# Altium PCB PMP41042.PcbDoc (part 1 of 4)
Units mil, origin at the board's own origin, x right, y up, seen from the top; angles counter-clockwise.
Board outline 9847.6 x 4445 mil, 6 copper layers (Top Layer, Layer 1, Layer 2, Layer 3, Layer 4, Bottom Layer), stack 32.112 mil thick; 329 components, 129 nets, 1246 pads, 863 vias.
Unrouted connection lines stored in the file: 6.
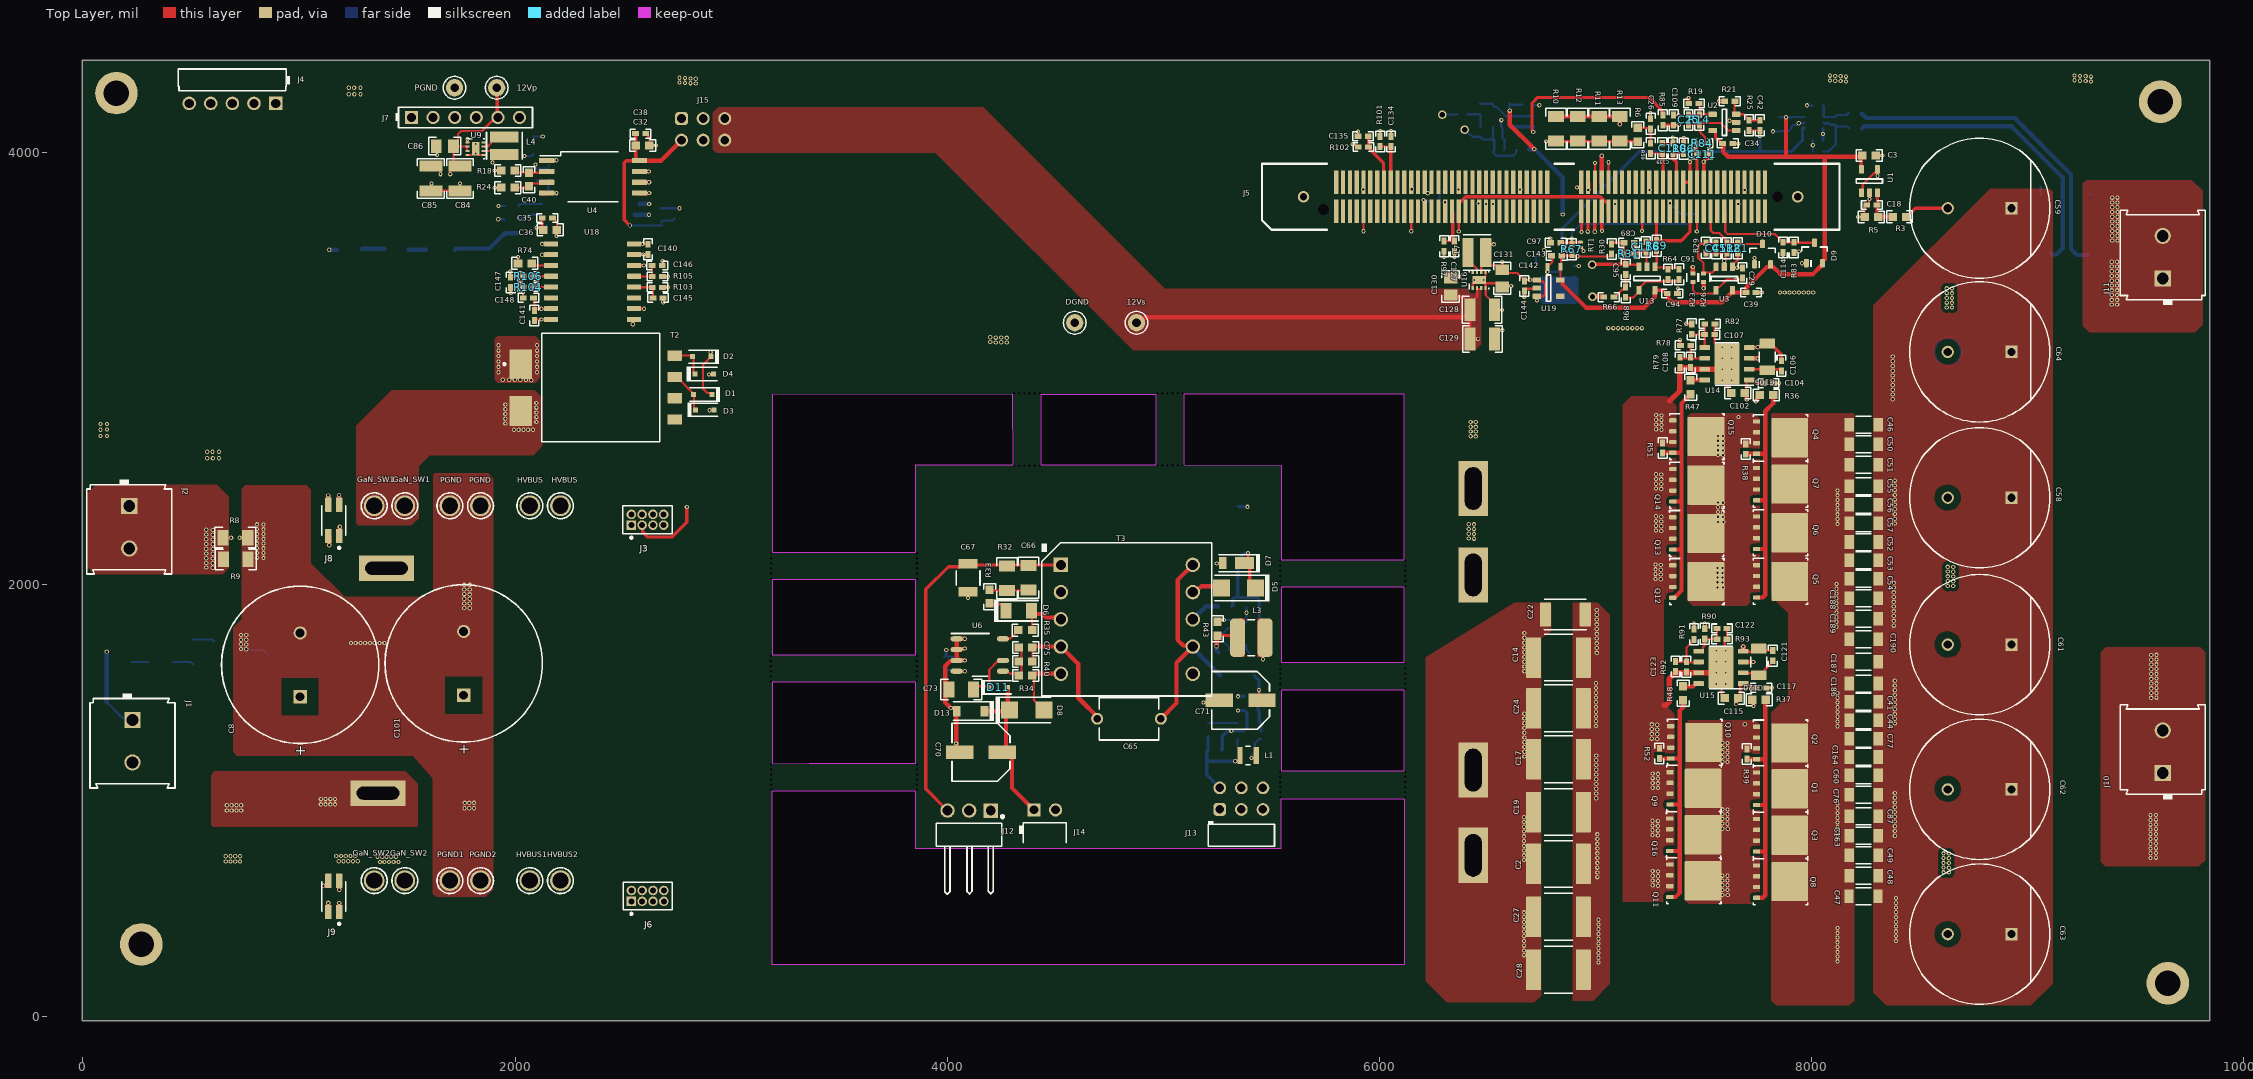
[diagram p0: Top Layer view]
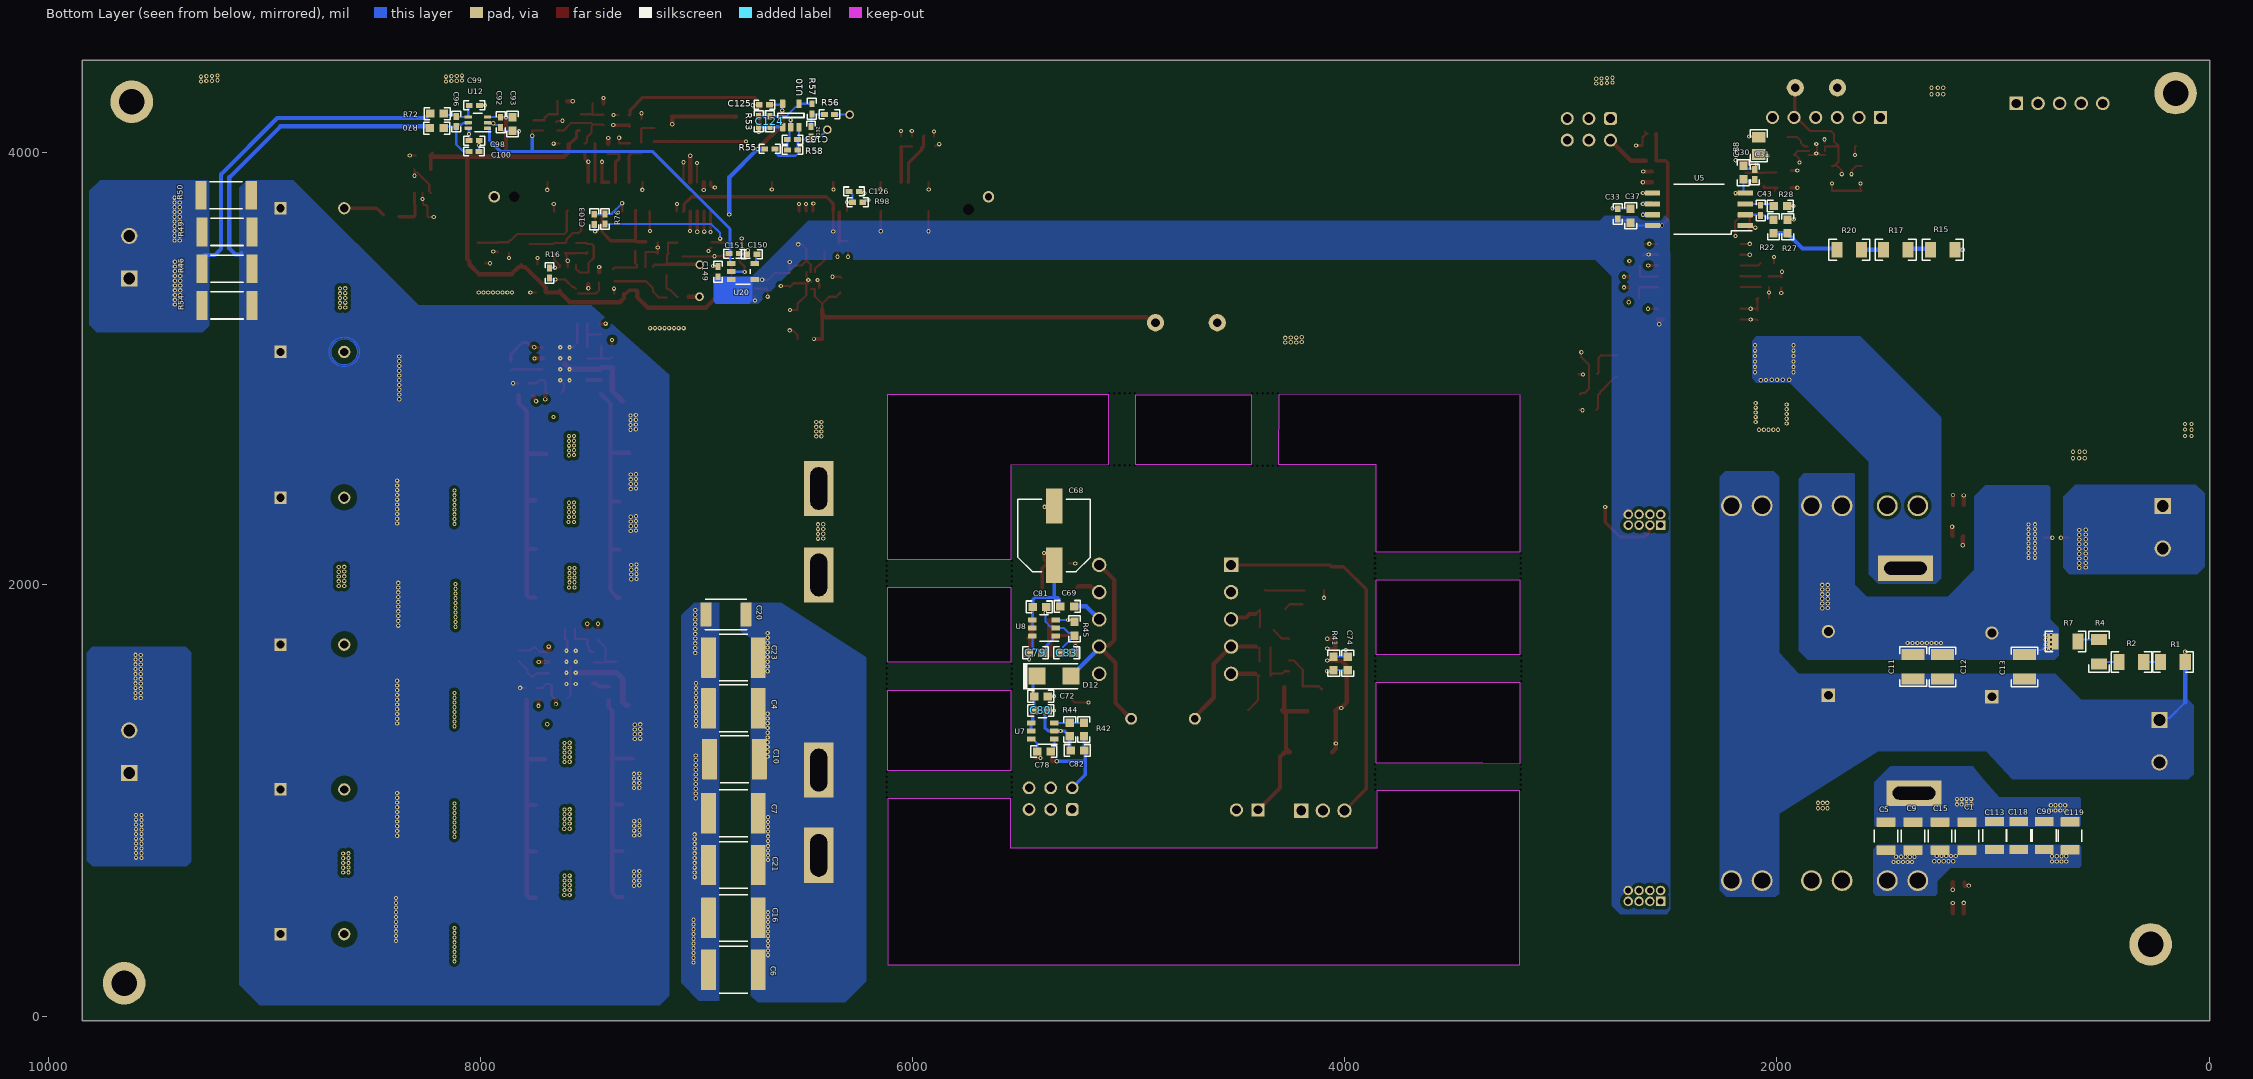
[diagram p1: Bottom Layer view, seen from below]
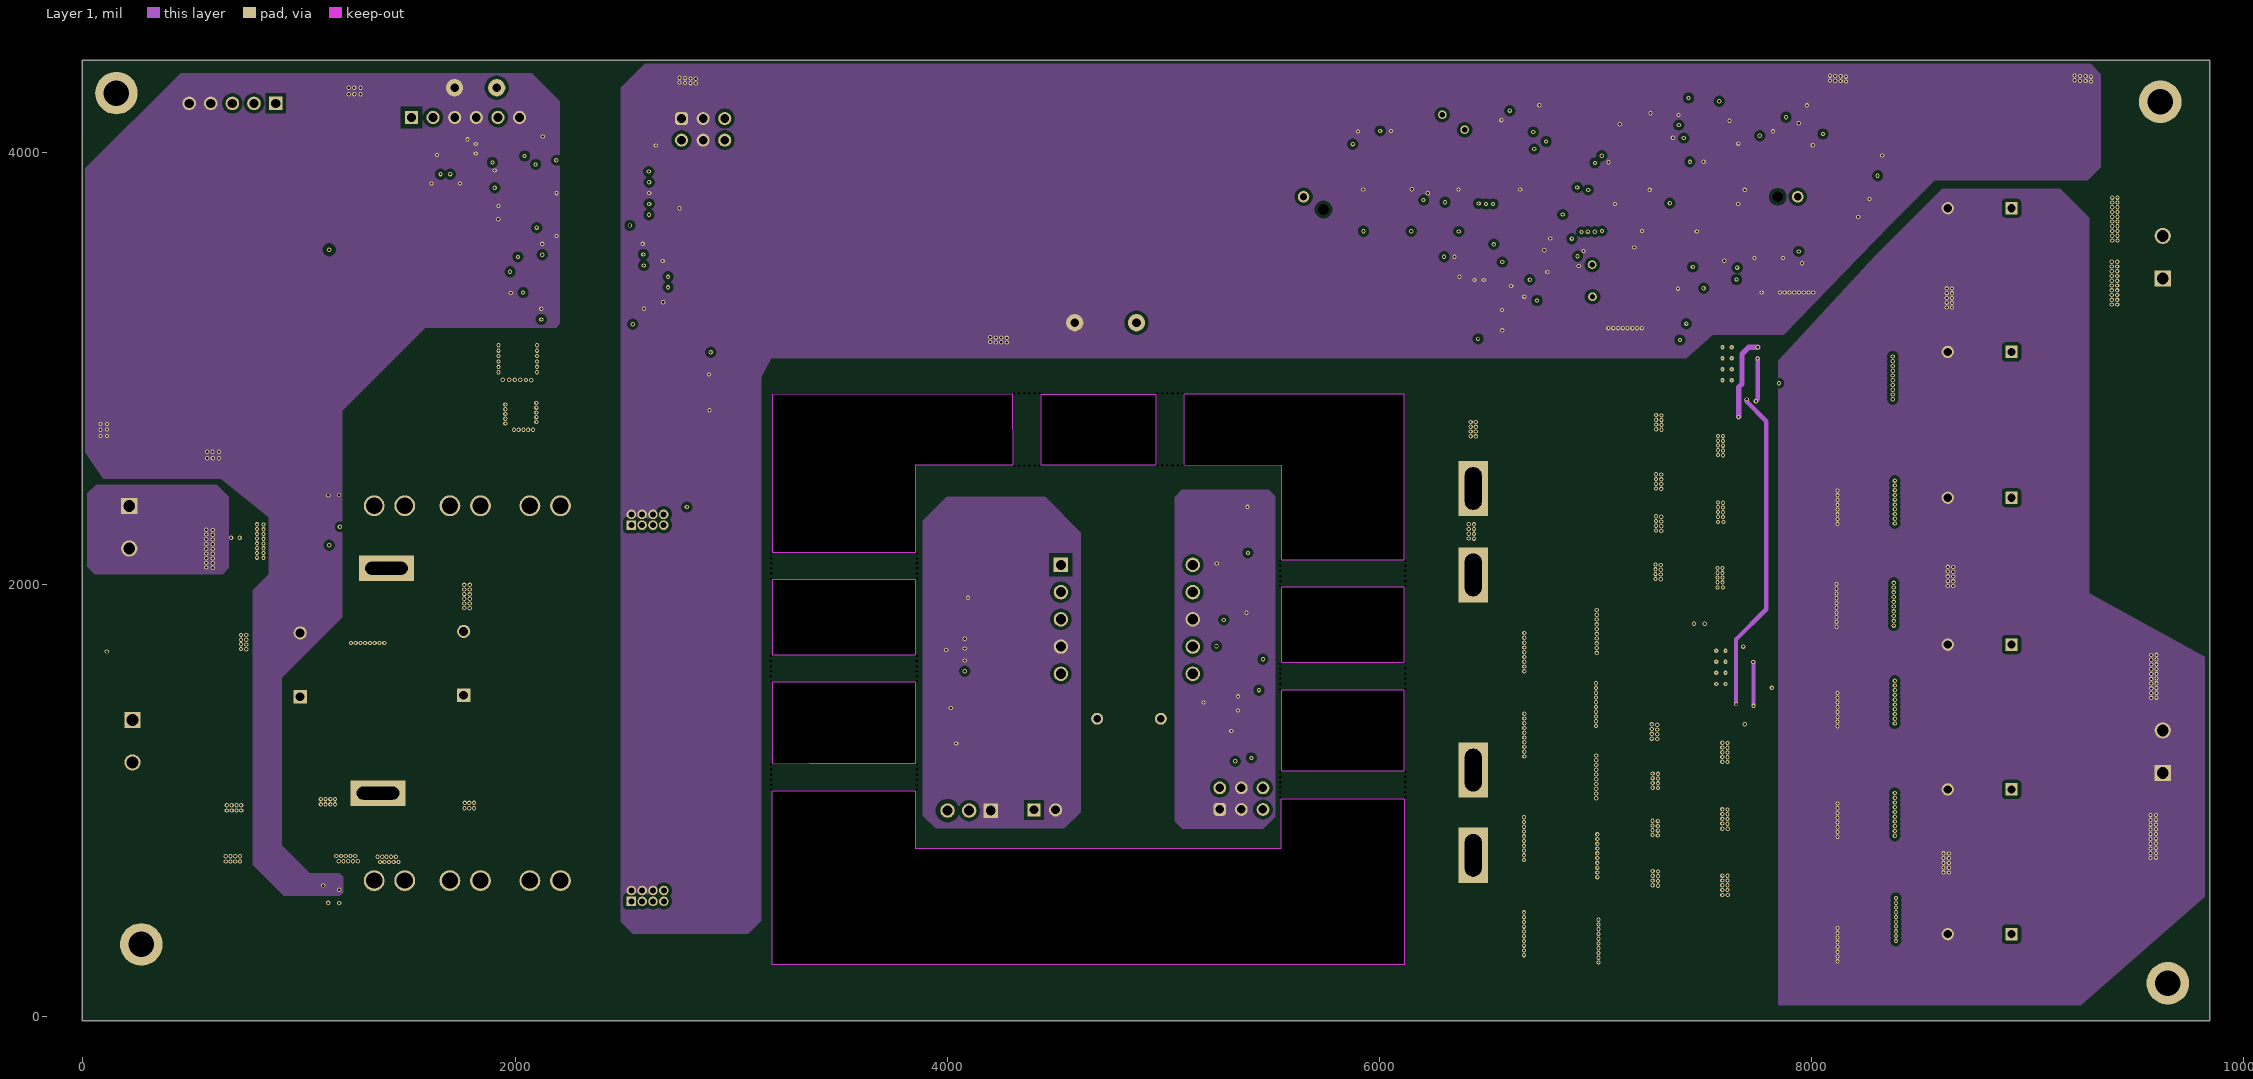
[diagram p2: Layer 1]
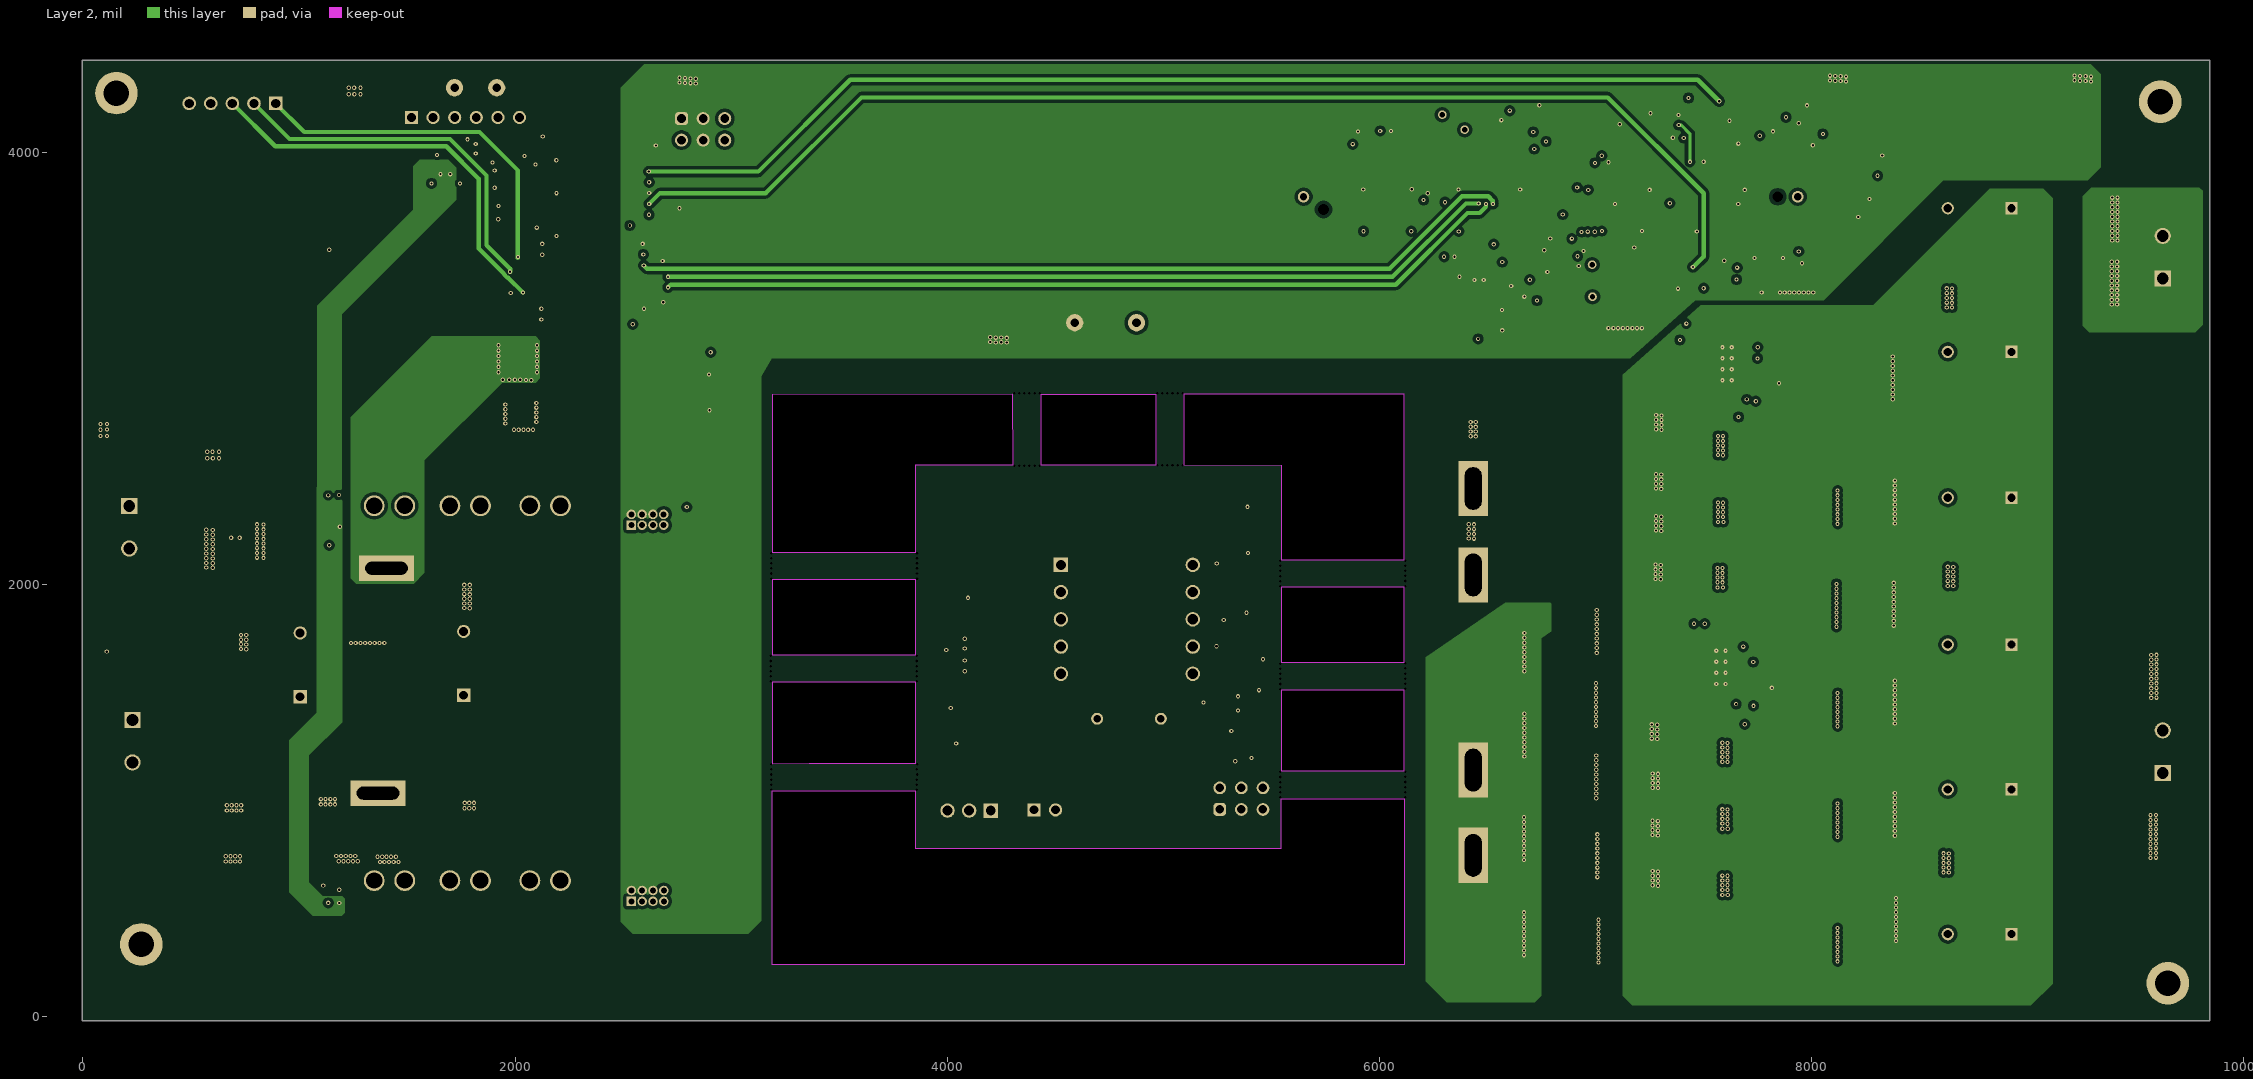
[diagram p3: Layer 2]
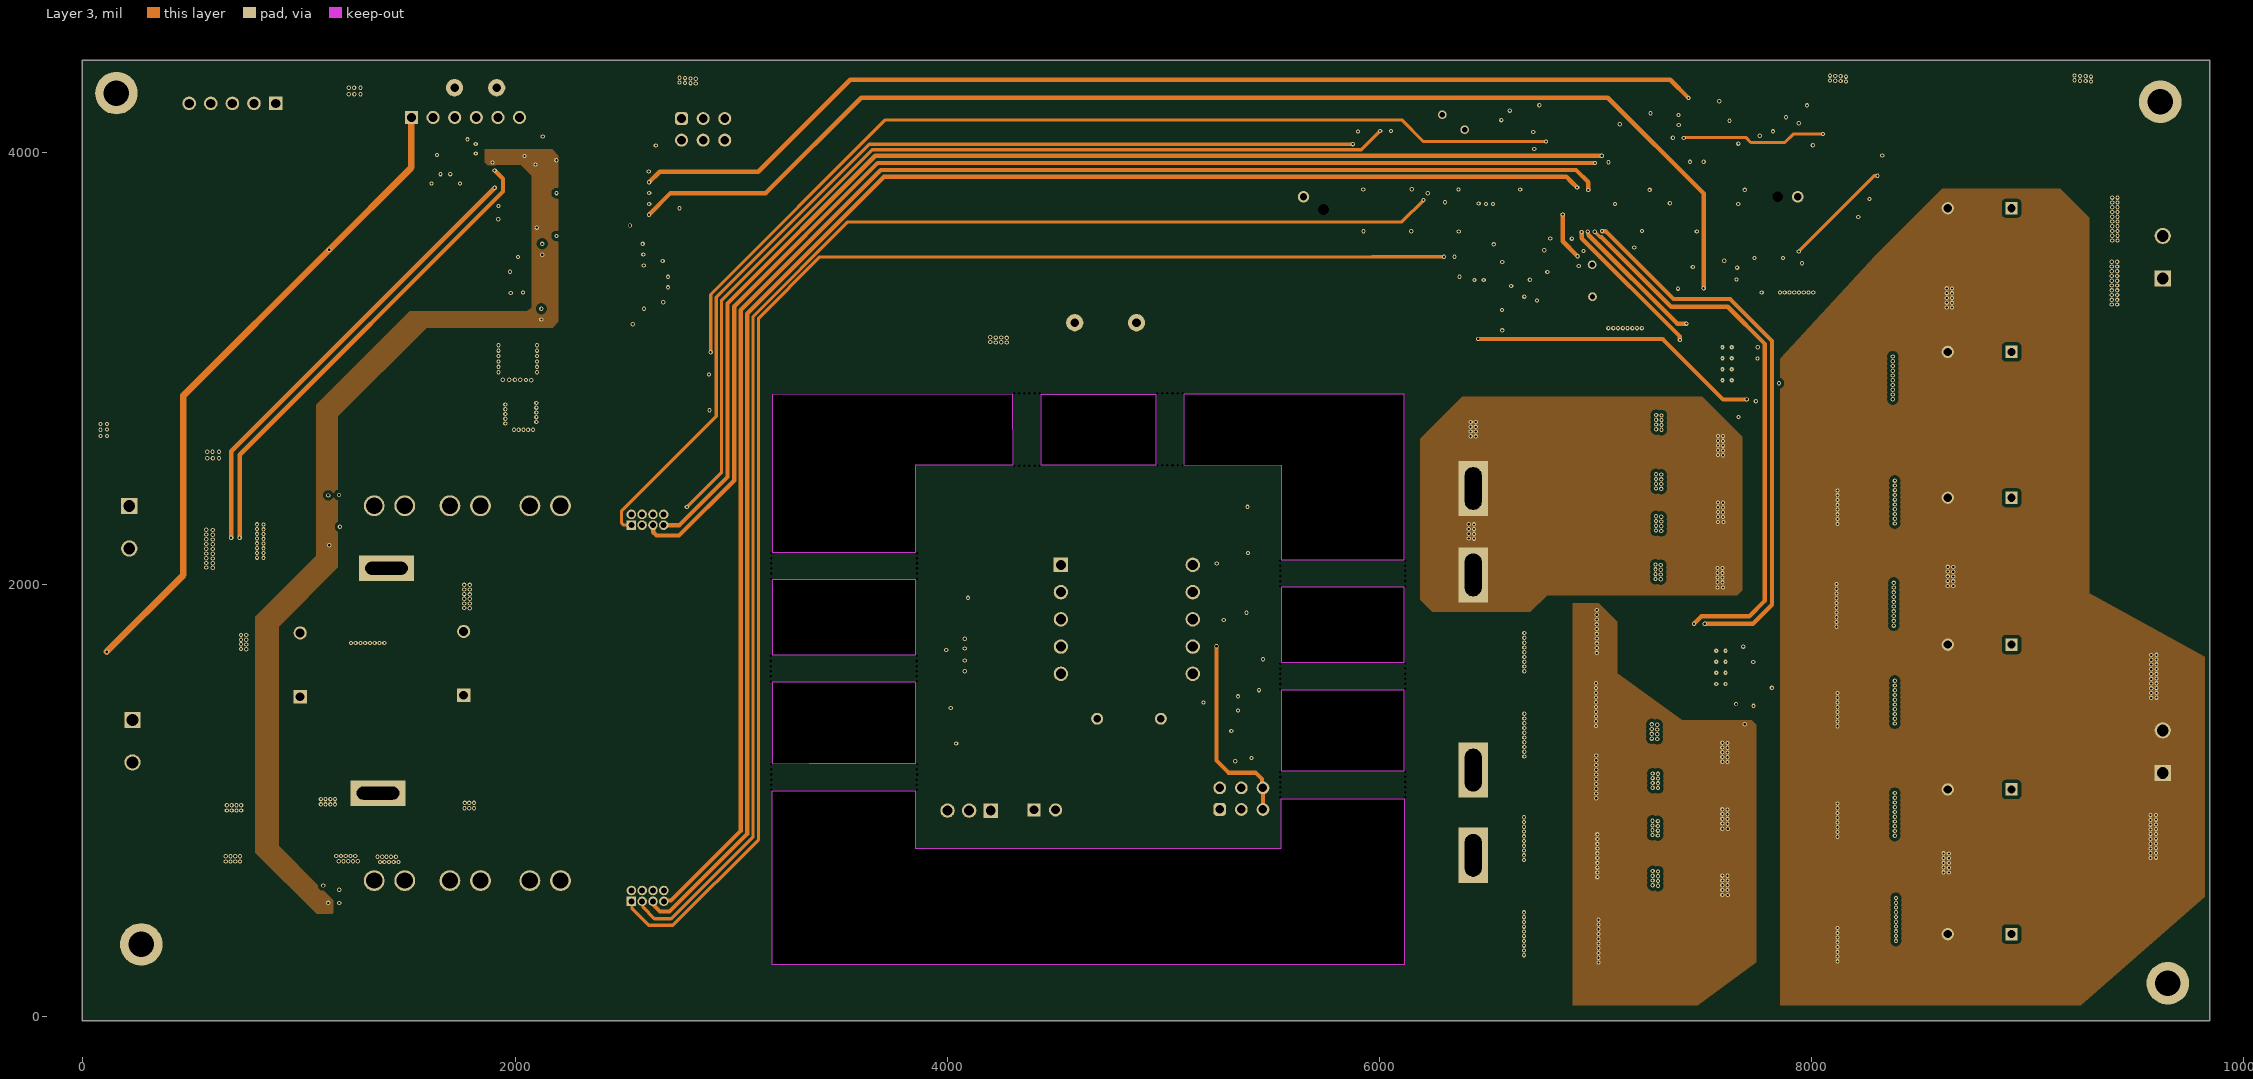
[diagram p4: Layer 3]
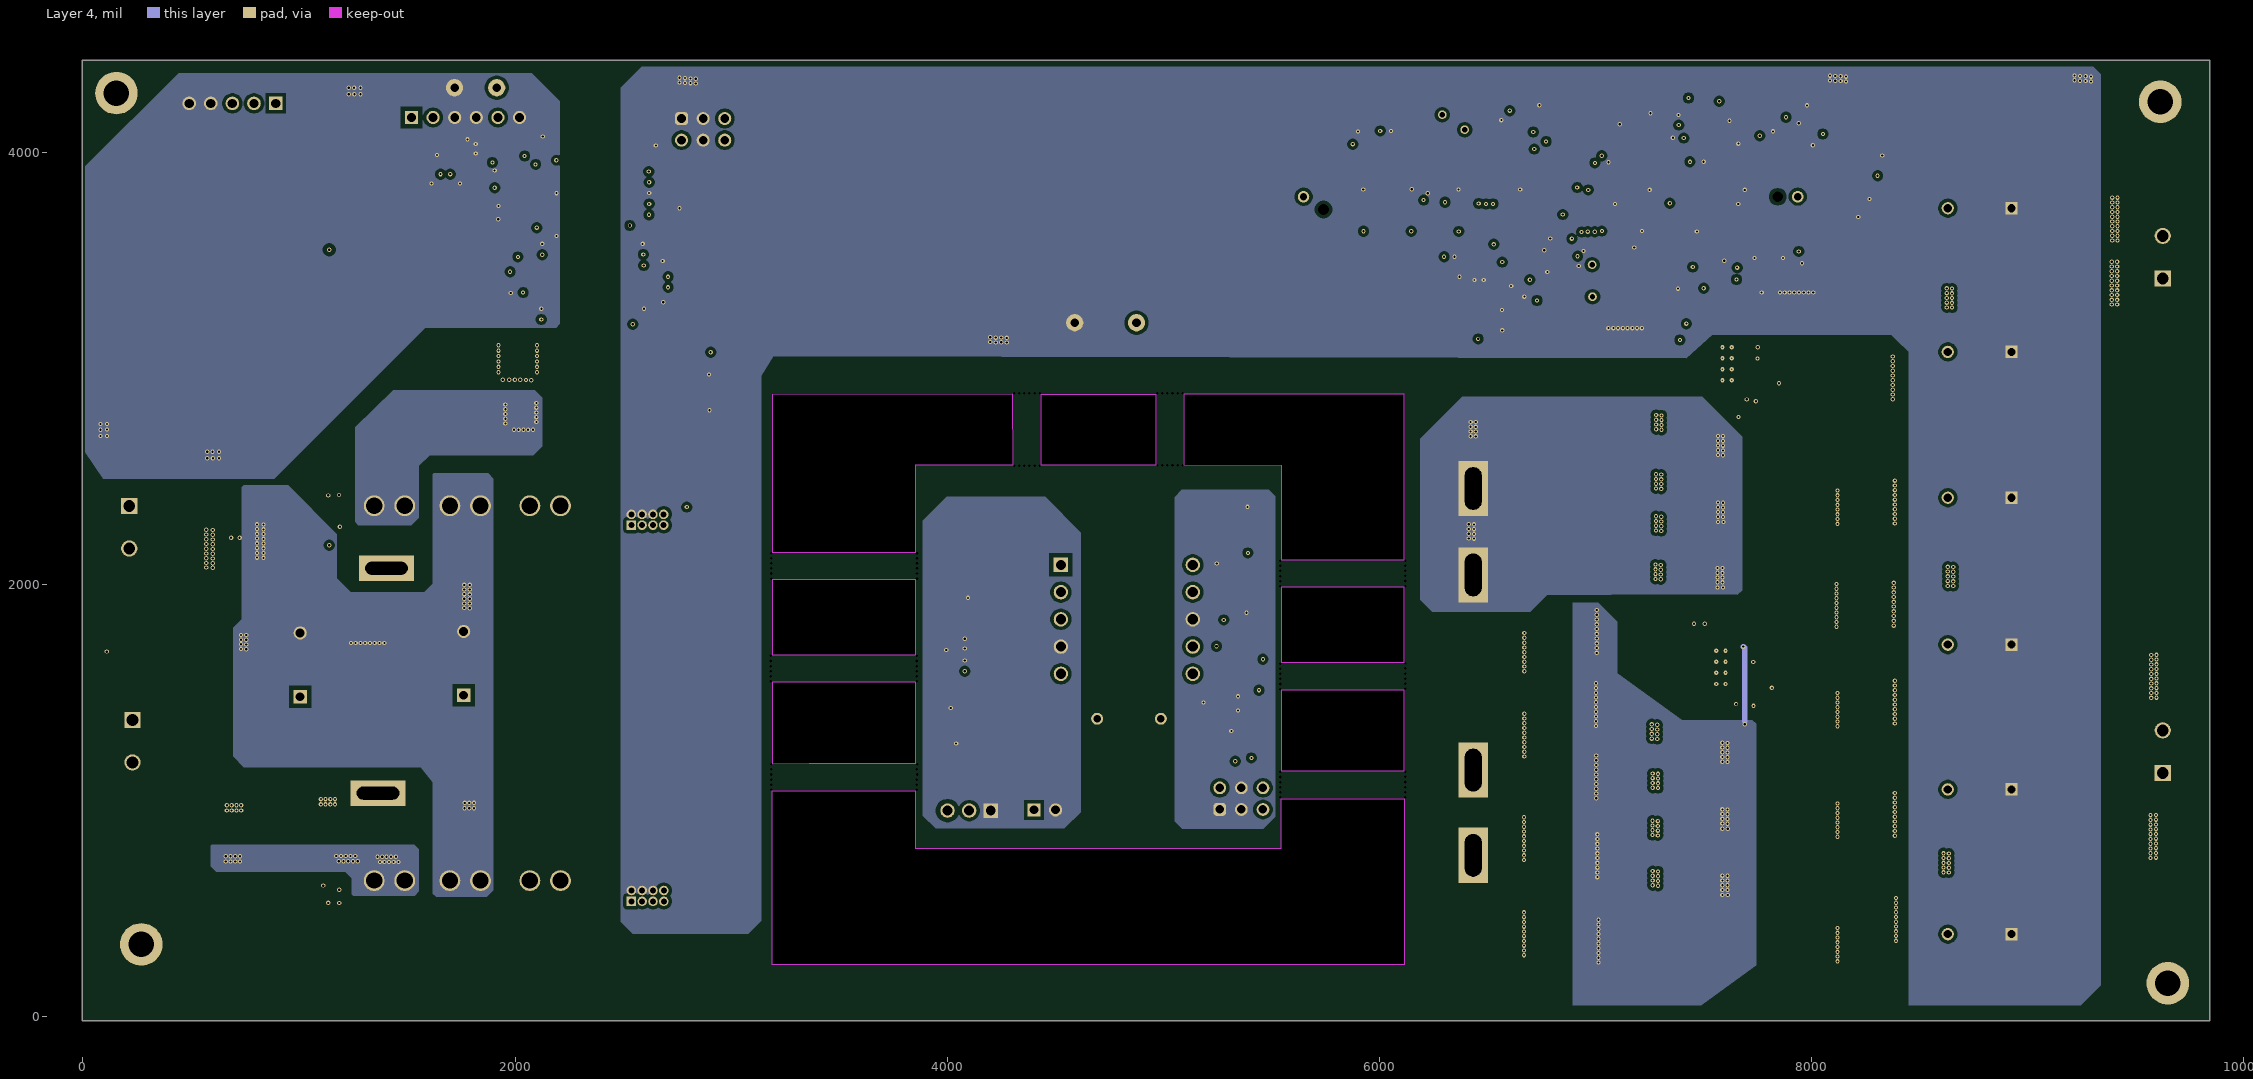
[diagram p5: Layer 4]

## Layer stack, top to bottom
Top Solder: solder mask 0.4, Solder Resist, Dk 3.5
Top Layer: signal copper 1.4
Dielectric 2: prepreg 2.8, PP-006, Dk 4.1
Layer 1: signal copper 1.378
Dielectric 4: prepreg 2.8, PP-006, Dk 4.1
Layer 2: signal copper 1.378
Dielectric 1: dielectric 12.6, FR-4, Dk 4.8
Layer 3: signal copper 1.378
Dielectric 5: prepreg 2.8, PP-006, Dk 4.1
Layer 4: signal copper 1.378
Dielectric 3: prepreg 2.8, PP-006, Dk 4.1
Bottom Layer: signal copper 1.4
Bottom Solder: solder mask 0.4, Solder Resist, Dk 3.5

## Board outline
-3.5,-17.72 9844.09,-17.72 9844.09,4427.28 -3.5,4427.28
cut-out: 3190.23,2151 3855,2151 3855,2554.34 4305.74,2555.07 4304.25,2881 3189.22,2880
cut-out: 3190,240 3190,1045 3852,1045 3852,780.5 5547,779.5 5547,1010 6115,1010 6115,240
cut-out: 3190,1675 3854.62,1675 3855.56,2023 3190,2023
cut-out: 3190.05,1172 3360.78,1174.05 3854.61,1172.97 3855.63,1548 3190.05,1548
cut-out: 4433,2554 4966.64,2554 4967.53,2880 4433,2880
cut-out: 5547,1138 6114.55,1138 6115.57,1512 5547,1512
cut-out: 5547,1640 6114.77,1640 6115.88,1988 5547,1988
cut-out: 5094.95,2555.27 5546.88,2553.67 5545.88,2115.47 6115,2116.22 6115.01,2881.03 5095.05,2880.64

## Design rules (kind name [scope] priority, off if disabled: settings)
Clearance Clearance_10 [InNet('NetT2_1') vs InNet('PGND') And OnLayer('Bottom Layer')] p1: gap=60 ignorepadtopadclearanceinfootprint=TRUE
Clearance Clearance_9 [InNet('NetC1_2') vs InNet('PGND') And OnLayer('Top Layer')] p2: gap=60 ignorepadtopadclearanceinfootprint=TRUE
Clearance Clearance_8 [InNet('NetC1_2') vs InNet('HVBUS')] p3: gap=60 ignorepadtopadclearanceinfootprint=TRUE
Clearance Clearance_7 [InNet('PGND') vs InNet('HVBUS')] p4: gap=60 ignorepadtopadclearanceinfootprint=TRUE except(20: THPad-Fill THPad-Poly THPad-Region Via-Fill Via-Poly Via-Region Fill-Hole Poly-Hole Region-Hole)
Clearance Clearance_6 [InNet('48Vo+') vs InNet('SGND') And OnLayer('Bottom Layer')] p5: gap=50 ignorepadtopadclearanceinfootprint=TRUE
Clearance Clearance_3 [InNet('48Vo+') vs InNet('SGND') And OnLayer('Top Layer')] p6: gap=50 ignorepadtopadclearanceinfootprint=TRUE
Clearance Clearance_5 [InNet('SGND') vs InNet('SEC_SW2')] p7: gap=30 ignorepadtopadclearanceinfootprint=TRUE
Clearance Clearance_4 [InNet('SGND') vs InNet('SEC_SW1')] p8: gap=30 ignorepadtopadclearanceinfootprint=TRUE
Clearance Clearance_2 [InPolygon] p9: gap=15 ignorepadtopadclearanceinfootprint=TRUE
Clearance Clearance_1 [All] p10: gap=8 ignorepadtopadclearanceinfootprint=FALSE except(5: THPad-THPad; 10: SMDPad-Fill SMDPad-Poly SMDPad-Region)
Clearance [InNet('GaN_SW1') vs InNet('PGND')] p11: gap=60 ignorepadtopadclearanceinfootprint=TRUE
ComponentClearance [All] p1: gap=10 collisioncheckmode=3 verticalgap=10 showdistances=FALSE donotcheckwithout3dbody=TRUE
Height [All] p1: minheight=0 maxheight=2000 prefheight=500
PolygonConnect [All] p1: connectstyle=Direct reliefconductorwidth=10 reliefentries=4 polygonreliefangle="90 Angle" airgapwidth=10
PolygonConnect PolygonConnect_1 [All] p2: connectstyle=Direct reliefconductorwidth=10 reliefentries=4 polygonreliefangle="90 Angle" airgapwidth=10
RoutingVias [All] p1: holewidth=28 width=50 viastyle="Through Hole" minholewidth=10 minwidth=16 maxholewidth=28 maxwidth=50
SolderMaskExpansion [All] p1: expansion=4 istentingtop=FALSE
UnRoutedNet [All] p1: checkbadconnections=TRUE
Width [All] p1: maxlimit=100 minlimit=6 preferedwidth=10
27 further rules are at their usual default settings.

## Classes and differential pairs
component class BIAS: 12Vp 12Vs C65 C66 C67 C68 C69 C70 C71 C72 C73 C74 C75 C78 C79 C80 C81 C82 C83 D5 D6 D7 D8 D11 D12 D13 DGND J7 J12 J13 J14 J15 L1 L3 PGND R32 R33 R34 R35 R40 R41 R42 R43 R44 R45 T3 U6 U7 U8
component class PMP41042_sheet2: C84 C85 C86 C88 C89 C91 C92 C93 C94 C95 C96 C97 C98 C99 C100 C102 C103 C104 C105 C106 C107 C108 C109 C110 C111 C112 C114 C115 C116 C117 C120 C121 C122 C123 C124 C125 C126 C127 C128 C129 C130 C131 C132 C133 C134 C135 C139 C140 C141 C142 C143 C144 C145 C146 C147 C148 C149 C150 C151 D9 D10 GaN_SW1 GaN_SW2 HVBUS HVBUS1 HVBUS2 J3 J4 J5 J6 J8 J9 L4 L7 PGND PGND1 PGND2 R30 R31 R53 R55 R56 R57 R58 R59 R64 R66 R67 R68 R70 R72 R74 R76 R77 R78 R79 R81 R82 R83 R84 R85 R86 R89 R90 R91 R92 R93 R97 R98 R101 R102 R103 R104 R105 R106 RT1 U9 U10 U12 U13 U14 U15 U16 U18 U19 U20
component class Header: J4 J13
net class MV: NetR15_1

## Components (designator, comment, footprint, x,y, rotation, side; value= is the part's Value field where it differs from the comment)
12Vp "5000" Keystone5000 1915,4300 r90 top
12Vs "5000" Keystone5000 4876.5,3212.28 r90 top
C1 "CGA6P1C0G3A103J250AC" FP-CGA6P1C0G3A103J250AC_1210-MFG 1120,835.87 r90 bottom value=10nF
C2 "CKG57NC0G2E304J500JH" FP-CKG57NC0G2E304J500JH_2220-MFG 6829.53,707.28 r0 top value=300nF
C3 "CL10B104KO8NNNC" 0603 8267.05,3985.98 r0 top value=0.1uF
C4 "CKG57NC0G2E304J500JH" FP-CKG57NC0G2E304J500JH_2220-MFG 6830.12,1427.28 r0 bottom value=300nF
C5 "CGA6P1C0G3A103J250AC" FP-CGA6P1C0G3A103J250AC_1210-MFG 1495,835.87 r90 bottom value=10nF
C6 "CKG57NC0G2E304J500JH" FP-CKG57NC0G2E304J500JH_2220-MFG 6830.12,217.28 r0 bottom value=300nF
C7 "CKG57NC0G2E304J500JH" FP-CKG57NC0G2E304J500JH_2220-MFG 6830.12,942.28 r0 bottom value=300nF
C8 "450BXW150MEFC18X45" BXW_1800x4500#1 1005.35,1628.83 r90 top value=150uF
C9 "CGA6P1C0G3A103J250AC" FP-CGA6P1C0G3A103J250AC_1210-MFG 1370,835.91 r90 bottom value=10nF
C10 "CKG57NC0G2E304J500JH" FP-CKG57NC0G2E304J500JH_2220-MFG 6824.96,1192.28 r0 bottom value=300nF
C11 "CGA6L1X7T2J104K160AC" 1210_200 1369.09,1620.2 r90 bottom value=0.1uF
C12 "CGA6L1X7T2J104K160AC" 1210_200 1234.09,1619.37 r90 bottom value=0.1uF
C13 "CGA6L1X7T2J104K160AC" 1210_200 854.09,1619.37 r90 bottom value=0.1uF
C14 "CKG57NC0G2E304J500JH" FP-CKG57NC0G2E304J500JH_2220-MFG 6829.53,1662.28 r0 top value=300nF
C15 "CGA6P1C0G3A103J250AC" FP-CGA6P1C0G3A103J250AC_1210-MFG 1245,835.87 r90 bottom value=10nF
C16 "CKG57NC0G2E304J500JH" FP-CKG57NC0G2E304J500JH_2220-MFG 6830.12,457.28 r0 bottom value=300nF
C17 "CKG57NC0G2E304J500JH" FP-CKG57NC0G2E304J500JH_2220-MFG 6829.53,1192.28 r0 top value=300nF
C18 "GRM1555C1H471JA01D" 0402 8280.12,3757.28 r180 top value=470pF
C19 "CKG57NC0G2E304J500JH" FP-CKG57NC0G2E304J500JH_2220-MFG 6829.53,947.28 r0 top value=300nF
C20 "C4532C0G2E104J320KN" FP-C4532C0G2E104J320KN_1812-MFG 6864.96,1862.28 r0 bottom value=100nF
C21 "CKG57NC0G2E304J500JH" FP-CKG57NC0G2E304J500JH_2220-MFG 6830.12,702.28 r0 bottom value=300nF
C22 "C4532C0G2E104J320KN" FP-C4532C0G2E104J320KN_1812-MFG 6861.02,1862.28 r0 top value=100nF
C23 "CKG57NC0G2E304J500JH" FP-CKG57NC0G2E304J500JH_2220-MFG 6830.12,1662.28 r0 bottom value=300nF
C24 "CKG57NC0G2E304J500JH" FP-CKG57NC0G2E304J500JH_2220-MFG 6829.53,1427.28 r0 top value=300nF
C25 "GCM155R71E103KA37D" 0402 7431.5,4151.06 r90 top value=0.01uF
C26 "GRM1555C1H100JA01D" 0402 7256,4133 r90 top value=10pF
C27 "CKG57NC0G2E304J500JH" FP-CKG57NC0G2E304J500JH_2220-MFG 6829.53,462.28 r0 top value=300nF
C28 "CKG57NC0G2E304J500JH" FP-CKG57NC0G2E304J500JH_2220-MFG 6829.53,217.28 r0 top value=300nF
C29 "CC0402KRX7R7BB103" 0402 7681.5,3442.28 r90 top value=0.01uF
C30 "CGA3E1X7R1C105K080AC" 0603 2155.47,3907.28 r270 bottom value=1uF
C31 "GRM155R71E104KE14D" 0402 2102.5,3898.25 r270 bottom value=0.1uF
C32 "CGA3E1X7R1C105K080AC" 0603 2590.47,4032.28 r0 top value=1uF
C33 "GRM155R71E104KE14D" 0402 2736.77,3716.06 r90 bottom value=0.1uF
C34 "GRM155R71E104KE14D" 0402 7612.87,4042.28 r0 top value=0.1uF
C35 "GRM155R71E104KE14D" 0402 2149.09,3697.28 r0 top value=0.1uF
C36 "GRM188Z71C475KE21D" 0603 2161.97,3642.28 r0 top value=4.7uF
C37 "GRM188Z71C475KE21D" 0603 2676.77,3707.28 r90 bottom value=4.7uF
C38 "GRM155R71E104KE14D" 0402 2580.79,4087.28 r0 top value=0.1uF
C39 "GRM155R71E104KE14D" 0402 7720.67,3352.28 r0 top value=0.1uF
C40 "GRM188R71E103KA01D" 0603 2063.9,3874.41 r270 top value=0.01uF
C41 "GRM31CR72A225KA73L" 1206_190 8241.97,1457.28 r0 top value=2.2uF
C42 "GCM155R71E103KA37D" 0402 7761.5,4126.06 r270 top value=0.01uF
C43 "CC0402KRX7R7BB103" 0402 2075.47,3732.28 r90 bottom value=0.01uF
C44 "GRM31CR72A225KA73L" 1206_190 8241.97,1372.28 r0 top value=2.2uF
C45 "CC0402KRX7R7BB103" 0402 7559.09,3557.28 r270 top value=0.01uF
C46 "GRM31CR72A225KA73L" 1206_190 8241.97,2739.87 r0 top value=2.2uF
C47 "GRM31CR72A225KA73L" 1206_190 8241.5,557.28 r0 top value=2.2uF
C48 "GRM31CR72A225KA73L" 1206_190 8241.97,652.28 r0 top value=2.2uF
C49 "GRM31CR72A225KA73L" 1206_190 8241.97,747.28 r0 top value=2.2uF
C50 "GRM31CR72A225KA73L" 1206_190 8241.97,2649.87 r0 top value=2.2uF
C51 "GRM31CR72A225KA73L" 1206_190 8241.97,2554.87 r0 top value=2.2uF
C52 "GRM31CR72A225KA73L" 1206_190 8241.97,2197.28 r0 top value=2.2uF
C53 "GRM31CR72A225KA73L" 1206_190 8241.97,2112.28 r0 top value=2.2uF
C54 "GRM31CR72A225KA73L" 1206_190 8241.97,2027.28 r0 top value=2.2uF
C55 "GRM31CR72A225KA73L" 1206_190 8241.97,2454.87 r0 top value=2.2uF
C56 "GRM31CR72A225KA73L" 1206_190 8241.97,2369.87 r0 top value=2.2uF
C57 "GRM31CR72A225KA73L" 1206_190 8241.97,2284.87 r0 top value=2.2uF
C58 "EGPD800ELL102ML35H" FP-EGPD800ELL102ML35H_RADIAL-MFG 8779.09,2402.28 r180 top value=1mF
C59 "EGPD800ELL102ML35H" FP-EGPD800ELL102ML35H_RADIAL-MFG 8779.09,3742.28 r180 top value=1mF
C60 "GRM31CR72A225KA73L" 1206_190 8241.97,1117.28 r0 top value=2.2uF
C61 "EGPD800ELL102ML35H" FP-EGPD800ELL102ML35H_RADIAL-MFG 8779.09,1722.28 r180 top value=1mF
C62 "EGPD800ELL102ML35H" FP-EGPD800ELL102ML35H_RADIAL-MFG 8779.09,1052.28 r180 top value=1mF
C63 "EGPD800ELL102ML35H" FP-EGPD800ELL102ML35H_RADIAL-MFG 8779.09,382.28 r180 top value=1mF
C64 "EGPD800ELL102ML35H" FP-EGPD800ELL102ML35H_RADIAL-MFG 8779.09,3077.28 r180 top value=1mF
C65 "DE11XKX470JN4AC05F" KY_700x500x1000 4841.61,1379.33 r180 top value=47pF
C66 "GRM31BR72J103KW01L" 1206 4376.61,2031.41 r270 top value=0.01uF
C67 "C1210C104KBRAC7800" 1210_280 4096.61,2031.41 r270 top value=0.1uF
C68 "25SVPF100M" SVPF_E7 5345,2227 r90 bottom value=100uF
C69 "GCJ188R71E104KA12D" 0603 5284.96,1899.33 r180 bottom value=0.1uF
C70 "EEEFTE221XAP" Panasonic_D8 4156.61,1224.33 r180 top value=220uF
C71 "EEE-FTA471XAP" Panasonic_D8 5358.19,1464.33 r180 top value=470uF
C72 "GCJ188R71E104KA12D" 0603 5406.61,1482.87 r180 bottom value=0.1uF
C73 "C3216JB1E476M160AC" 1206 4064.52,1514.33 r180 top value=47uF
C74 "C0603C101J5GAC" 0603 3986.61,1635.82 r90 bottom value=100pF
C75 "GRM1885C1H560JA01D" 0603 4363.11,1709.33 r0 top value=56pF
C76 "GRM31CR72A225KA73L" 1206_190 8241.97,1027.28 r0 top value=2.2uF
C77 "GRM31CR72A225KA73L" 1206_190 8241.97,1287.28 r0 top value=2.2uF
C78 "C1608X7R1E104K080AA" 0603 5393.11,1227.87 r180 bottom value=0.1uF
C79 "C1608X7R1E104K080AA" 0603 5431.61,1684.33 r180 bottom value=0.1uF
C80 "GRM188R61E475KE11D" 0603 5406.61,1417.87 r180 bottom value=4.7uF
C81 "GRM188R61E475KE11D" 0603 5414,1897 r180 bottom value=4.7uF
C82 "C1608X5R1A226M080AC" 0603 5238.11,1232.87 r0 bottom value=22uF
C83 "GRT188R61E106ME13D" 0603 5288.11,1684.33 r0 bottom value=10uF
C84 "GRM32ER61C476KE15L" 1210_270 1745,3880 r90 top value=47uF
C85 "GRM32ER61C476KE15L" 1210_270 1610,3880 r90 top value=47uF
C86 "GRM219R71E105KA88D" 0805_HV 1675,4030 r180 top value=1uF
C87 "GRM31CR72A225KA73L" 1206_190 8241.97,927.28 r0 top value=2.2uF
C88 "CL21A226KOQNNNE" 0805_HV 2084,4031 r90 bottom value=22uF
C89 "CGA2B3X7R1E104K050BB" 0402 7156.85,3582.28 r0 top value=0.1uF
C90 "CGA6P1C0G3A103J250AC" FP-CGA6P1C0G3A103J250AC_1210-MFG 762,838.96 r90 bottom value=10nF
C91 "GRM1555C1H2R2CA01D" 0402 7388.09,3436.32 r270 top value=2.2pF
C92 "GRM155R71E104KE14D" 0402 7907.72,4139.87 r90 bottom value=0.1uF
C93 "CGA3E1X7R1C105K080AC" 0603 7852.72,4132 r90 bottom value=1uF
C94 "GRM155R71E104KE14D" 0402 7356.5,3347.28 r180 top value=0.1uF
C95 "CL05B103KA5NNNC" 0402 7141,3459 r90 top value=0.01uF
C96 "GRM155R71E333KA88D" 0402 8112.72,4143.5 r90 bottom value=0.033uF
C97 "CGA2B2X7R1H471K050BA" 0402 6816.5,3582.28 r180 top value=470pF
C98 "CC0402JRNPO9BN101" 0402 8029.82,4055.23 r180 bottom value=100pF
C99 "CL05B102KB5NNNC" 0402 8029.09,4218.5 r180 bottom value=1000pF
C100 "CL05B102KB5NNNC" 0402 8030.53,4004.64 r180 bottom value=1000pF
C101 "450BXW150MEFC18X45" BXW_1800x4500#2 1762,1635.64 r90 top value=150uF
C102 "GRM188Z71C475KE21D" 0603 7660,2887.28 r0 top value=4.7uF
C103 "GRM155R71E104KE14D" 0402 7474.09,3690.91 r90 bottom value=0.1uF
C104 "CGA2B3X7R1E104K050BB" 0402 7801.5,2932.28 r180 top value=0.1uF
C105 "GRM31CC72A475KE11L" FP-GRM31CC72A475KE11L_1206-MFG 7796.5,3054.21 r270 top value=4.7µF
C106 "GRM155R62A104KE14D" 0402 7861.5,3012.83 r90 top value=0.1uF
C107 "CC0402JRNPO9BN101" 0402 7528.9,3157.28 r0 top value=100pF
C108 "CC0402JRNPO9BN101" 0402 7441.5,3028.66 r270 top value=100pF
C109 "GRM1555C1H100JA01D" 0402 7362.65,4149.62 r270 top value=10pF
C110 "GRM155R71E104KE14D" 0402 7359,4019.62 r90 top value=0.1uF
C111 "CL05B102KB5NNNC" 0402 7495.12,3992.28 r180 top value=1000pF
C112 "GRM155R71E104KE14D" 0402 7609.09,3557.28 r90 top value=0.1uF
C113 "CGA6P1C0G3A103J250AC" FP-CGA6P1C0G3A103J250AC_1210-MFG 993,838.96 r90 bottom value=10nF
C114 "GRM155R71E104KE14D" 0402 7869.09,3560.91 r90 top value=0.1uF
C115 "GRM188Z71C475KE21D" 0603 7630,1474.69 r0 top value=4.7uF
C116 "CC0402JRNPO9BN101" 0402 7234.09,3563.35 r270 top value=100pF
C117 "CGA2B3X7R1E104K050BB" 0402 7767.87,1522.28 r180 top value=0.1uF
C118 "CGA6P1C0G3A103J250AC" FP-CGA6P1C0G3A103J250AC_1210-MFG 880,838.96 r90 bottom value=10nF
C119 "CGA6P1C0G3A183J250AC" FP-CGA6P1C0G3A103J250AC_1210-MFG 643,837.96 r90 bottom value=10nF
C120 "GRM31CC72A475KE11L" FP-GRM31CC72A475KE11L_1206-MFG 7756.5,1642.28 r270 top value=4.7µF
C121 "GRM155R62A104KE14D" 0402 7821.5,1670.91 r90 top value=0.1uF
C122 "CC0402JRNPO9BN101" 0402 7586.5,1797.28 r0 top value=100pF
C123 "CC0402JRNPO9BN101" 0402 7371.5,1621.06 r270 top value=100pF
C124 "GRM1555C1H2R2CA01D" 0402 6661,4144.38 r90 bottom value=2.2pF
C125 "GRM155R71E104KE14D" 0402 6686.62,4221 r180 bottom value=0.1uF
C126 "CC0402JRNPO9BN101" 0402 6271.38,3820 r180 bottom value=100pF
C127 "CC0402JRNPO9BN101" 0402 6348.19,3566.65 r270 top value=100pF
C128 "GRM32ER61C476KE15L" 1210_270 6476.18,3272.28 r180 top value=47uF
C129 "GRM32ER61C476KE15L" 1210_270 6477.01,3137.28 r180 top value=47uF
C130 "GRM219R71E105KA88D" 0805_HV 6330,3380 r90 top value=1uF
C131 "CL21A226KOQNNNE" 0805_HV 6569.09,3417.28 r270 top value=22uF
C132 "CL05B103KA5NNNC" 0402 6471,4097 r270 bottom value=0.01uF
C133 "CGA2B3X7R1E104K050BB" 0402 6557,4060 r0 bottom value=0.1uF
C134 "CC0402JRNPO9BN101" 0402 6054.09,4050.91 r90 top value=100pF
C135 "CC0402JRNPO9BN101" 0402 5925.12,4075.59 r180 top value=100pF
C139 "GRM1555C1H100JA01D" 0402 7310,4019.59 r270 top value=10pF
C140 "C1005X7R1H104K050BB" 0402 2615.47,3552.28 r270 top value=0.1uF
C141 "C1005X7R1H104K050BB" 0402 2089.09,3245.91 r90 top value=0.1uF
C142 "CGA3E1X7R1E105K080AC" 0603S 6809.09,3472.28 r180 top value=1uF
C143 "GRM155R71E104KE14D" 0402 6821.18,3522.28 r180 top value=0.1uF
C144 "GRM155R71E104KE14D" 0402 6671.5,3382.28 r270 top value=0.1uF
C145 "GRM1555C1H100JA01D" 0402 2661.5,3327.28 r0 top value=10pF
C146 "GRM1555C1H100JA01D" 0402 2657.87,3477.28 r0 top value=10pF
C147 "GRM1555C1H100JA01D" 0402 1979.68,3398.94 r270 top value=10pF
C148 "GRM1555C1H100JA01D" 0402 2061.65,3327.28 r0 top value=10pF
C149 "GRM155R71E104KE14D" 0402 6901.5,3448.66 r90 bottom value=0.1uF
C150 "GRM155R71E104KE14D" 0402 6744.84,3529.09 r0 bottom value=0.1uF
C151 "GRM155R71E104KE14D" 0402 6826.18,3532.28 r180 bottom value=0.1uF
C163 "GRM31CR72A225KA73L" 1206_190 8241.97,837.28 r0 top value=2.2uF
C164 "GRM31CR72A225KA73L" 1206_190 8241.97,1202.28 r0 top value=2.2uF
C186 "GRM31CR72A225KA73L" 1206_190 8241.97,1542.28 r0 top value=2.2uF
C187 "GRM31CR72A225KA73L" 1206_190 8241.97,1642.28 r0 top value=2.2uF
C188 "GRM31CR72A225KA73L" 1206_190 8241.97,1937.28 r0 top value=2.2uF
C189 "GRM31CR72A225KA73L" 1206_190 8241.97,1842.28 r0 top value=2.2uF
C190 "GRM31CR72A225KA73L" 1206_190 8241.97,1747.28 r0 top value=2.2uF
D1 "BAS316,115" SOD-323 2868.5,2880.28 r180 top value=100V
D2 "BAS316,115" SOD-323 2863.69,3055.1 r180 top value=100V
D3 "BAS316,115" SOD-323 2878,2809 r0 top value=100V
D4 "BAS316,115" SOD-323 2875.31,2975 r0 top value=100V
D5 "B1100-13-F" SMA 5347.87,1984.33 r180 top value=100V
D6 "CRF03" SOD-123H 4331.61,1879.33 r0 top value=600V
D7 "DFLZ24-7" PowerDI123 5326.41,2099.33 r180 top value=24V
D8 "B170-13-F" SMA 4368.3,1419.33 r0 top value=70V
D9 "BAT54S-7-F" SOT-23 8014.09,3535.04 r90 top value=30V
D10 "BAT54S-7-F" SOT-23 7774.09,3529.53 r90 top value=30V
D11 "BAS316,115" SOD-323 4236.61,1524.33 r0 top value=100V
D12 "B250A-13-F" SMA 5345.86,1576.34 r180 bottom value=50V
D13 "CRZ18(TE85L,Q,M)" SOD-123 4108.3,1414.33 r180 top value=18V
DGND "5001" Keystone5001 4590.47,3212.28 r90 top
GaN_SW1 "0312-0-15-15-34-27-10-0" Mill-Max_0312-0-15-15-34-27-10-0 1347.8,2365 r90 top
GaN_SW1 "0312-0-15-15-34-27-10-0" Mill-Max_0312-0-15-15-34-27-10-0 1489.53,2365 r90 top
GaN_SW2 "0312-0-15-15-34-27-10-0" Mill-Max_0312-0-15-15-34-27-10-0 1347.8,629.92 r90 top
GaN_SW2 "0312-0-15-15-34-27-10-0" Mill-Max_0312-0-15-15-34-27-10-0 1489.53,629.92 r90 top
HVBUS "0312-0-15-15-34-27-10-0" Mill-Max_0312-0-15-15-34-27-10-0 2210,2365 r90 top
HVBUS "0312-0-15-15-34-27-10-0" Mill-Max_0312-0-15-15-34-27-10-0 2068.27,2365 r90 top
HVBUS1 "0312-0-15-15-34-27-10-0" Mill-Max_0312-0-15-15-34-27-10-0 2068.27,629.92 r90 top
HVBUS2 "0312-0-15-15-34-27-10-0" Mill-Max_0312-0-15-15-34-27-10-0 2210,629.92 r90 top
J1 "282856-2" TE_282856-2#1 229.09,1275.71 r270 top
J2 "282856-2" TE_282856-2#2 214.09,2265.71 r270 top
J3 "M50-3000445" FP-M50-3000445_CONN_SCKT_STRP8-MFG 2612.99,2300.39 r0 top
J4 "61300511021" Wurth_61300511021 691.5,4227.28 r180 top
J5 "HSEC8-160-01-L-DV-A-BL" controlCARD-120HSEC 6865.87,3796.22 r180 top
J6 "M50-3000445" FP-M50-3000445_CONN_SCKT_STRP8-MFG 2613.39,559.24 r0 top
J7 "SSW-106-01-T-S" Samtec_SSW-106-01-x-S 1770.47,4162.28 r0 top
J8 "FLE-102-01-G-DV" FP-FLE-102-01-G-DV_HDR4-MFG 1160.63,2297.46 r180 top
J9 "FLE-102-01-G-DV" FP-FLE-102-01-G-DV_HDR4-MFG 1160.63,557.09 r180 top
J10 "282856-2" TE_282856-2#2 9626.5,1227.28 r90 top
J11 "282856-2" TE_282856-2#2 9626.5,3515.71 r90 top
J12 "PEC03SBAN" Sullins_PEC03SBAN 4101.61,954.33 r180 top
J13 "90122-0763" Molex_90122-0763 5361.61,1009.33 r90 top
J14 "PEC02SBAN" Sullins_xxC02SBAN 4451.61,797.44 r0 top
J15 "PPPC032LFBN-RC" Sullins_xxxC032LFBN-RC 2870.47,4107.28 r0 top
L1 "74438323100" VLS252010HBX 5393.11,1209.17 r180 top value=10uH
L3 "784773118" WE-PD2A_4532 5407.63,1754.33 r180 top value=18uH
L4 "74438336022" FP-74438336010_SMD2-MFG 1950,4031.34 r270 top
L7 "74438336022" FP-74438336010_SMD2-MFG 6451.5,3537.28 r0 top
PGND "5001" Keystone5001 1720,4300 r90 top
PGND "0312-0-15-15-34-27-10-0" Mill-Max_0312-0-15-15-34-27-10-0 1839.92,2365 r90 top
PGND "0312-0-15-15-34-27-10-0" Mill-Max_0312-0-15-15-34-27-10-0 1698.19,2365 r90 top
PGND1 "0312-0-15-15-34-27-10-0" Mill-Max_0312-0-15-15-34-27-10-0 1698.19,629.92 r90 top
PGND2 "0312-0-15-15-34-27-10-0" Mill-Max_0312-0-15-15-34-27-10-0 1839.92,629.92 r90 top
Q1 "CSD19502Q5B" DNK0008A 7857.52,1055.16 r0 top value=80V
Q2 "CSD19502Q5B" DNK0008A 7857.52,1267.28 r0 top value=80V
Q3 "CSD19502Q5B" DNK0008A 7857.52,840.16 r0 top value=80V
Q4 "CSD19502Q5B" DNK0008A 7857.52,2680.16 r0 top value=80V
Q5 "CSD19502Q5B" DNK0008A 7857.52,2015.16 r0 top value=80V
Q6 "CSD19502Q5B" DNK0008A 7857.52,2240.16 r0 top value=80V
Q7 "CSD19502Q5B" DNK0008A 7857.52,2465.16 r0 top value=80V
Q8 "CSD19502Q5B" DNK0008A 7857.52,625.16 r0 top value=80V
Q9 "CSD19502Q5B" DNK0008A 7456.57,1057.28 r0 top value=80V
Q10 "CSD19502Q5B" DNK0008A 7460.04,1270.16 r0 top value=80V
Q11 "CSD19502Q5B" DNK0008A 7456.18,629.41 r0 top value=80V
Q12 "CSD19502Q5B" DNK0008A 7470.04,2014.41 r0 top value=80V
Q13 "CSD19502Q5B" DNK0008A 7469.09,2237.28 r0 top value=80V
Q14 "CSD19502Q5B" DNK0008A 7470.04,2460.16 r0 top value=80V
Q15 "CSD19502Q5B" DNK0008A 7470.04,2685.16 r0 top value=80V
Q16 "CSD19502Q5B" DNK0008A 7455.12,842.28 r0 top value=80V
R1 "CRCW1206100KFKEA" 1206 167.01,1642.28 r180 bottom value=100k
R2 "CRCW1206100KFKEA" 1206 359.09,1642.28 r180 bottom value=100k
R3 "CRCW060347K0FKEA" 0603 8407.99,3702.28 r0 top value=47.0k
R4 "CRCW1206100KFKEA" 1206 509.09,1689.37 r270 bottom value=100k
R5 "RT0603BRD072K1L" 0603 8277.72,3701.59 r0 top value=2.10k
R6 "MCT06030Z0000ZP500" 0603 7196.28,4082.5 r270 top value=0
R7 "CRCW1206100KFKEA" 1206 664.09,1737.28 r180 bottom value=100k
R8 "CRF1206-FZ-R004ELF" 1206 705.47,2217.28 r0 top value=0.004
R9 "CRF1206-FZ-R004ELF" 1206 707.56,2117.28 r0 top value=0.004
R10 "RC1206FR-0747RL" 1206 6818.28,4109.58 r270 top value=47.0
R11 "RC1206FR-0747RL" 1206 7018.28,4109.58 r270 top value=47.0
R12 "RC1206FR-0747RL" 1206 6918.28,4109.58 r270 top value=47.0
R13 "RC1206FR-0747RL" 1206 7113.28,4109.58 r270 top value=47.0
R14 "RC0402FR-074K7L" 0402 7481.5,4151.06 r270 top value=4.70k
R15 "ERJ-8ENF2003V" 1206 1232.09,3550 r180 bottom value=200k
R16 "CRCW040210K0DHEDP" 0402 7681.5,3442.28 r90 bottom value=10.0k
R17 "ERJ-8ENF2003V" 1206 1450,3550 r180 bottom value=200k
R18 "CRCW060310R0FKEA" 0603 1966.5,3917.28 r0 top value=10.0
R19 "RC0402FR-074K7L" 0402 7456.5,4227.28 r0 top value=4.70k
R20 "TNPW1206100KBEEA" 1206 1665,3550 r180 bottom value=100k
R21 "RC0402FR-074K7L" 0402 7622.72,4237.28 r0 top value=4.70k
R22 "CRCW06030000Z0EA" 0603 2015.47,3657.28 r90 bottom value=0
R23 "RT0402BRD076K34L" FP-RT0402BRD076K34L_0402-MFG 7451.5,3420.91 r270 top value=6.34k
R24 "CRCW060310R0FKEA" 0603 1966.5,3837.28 r0 top value=10.0
R25 "RC0402FR-074K7L" 0402 7711.5,4126.06 r90 top value=4.70k
R26 "RT0402BRD076K34L" FP-RT0402BRD076K34L_0402-MFG 7501.5,3420.91 r90 top value=6.34k
R27 "RT0603BRD072K1L" 0603 1950.47,3657.28 r270 bottom value=2.10k
R28 "CRCW06030000Z0EA" 0603 1983.98,3752.28 r0 bottom value=0
R29 "CRCW040210K0DHEDP" 0402 7511.65,3558.94 r90 top value=10.0k
R30 "CRCW040210K0FKED" 0402 7075.47,3553.66 r270 top value=10.0k
R31 "CRCW040210K0FKED" 0402 7155.47,3532.28 r180 top value=10.0k
R32 "CRCW1206150KFKEA" 1206 4276.61,2029.33 r90 top value=150k
R33 "CRCW060315R0JNEA" 0603 4196.61,1944.33 r90 top value=15
R34 "RC0603FR-0751K1L" 0603 4363.11,1579.33 r0 top value=51.1k
R35 "RC0603JR-070RL" 0603 4361.61,1789.33 r0 top value=0
R36 "CRCW06035R10JNEA" 0603 7791.5,2877.28 r0 top value=2.20
R37 "CRCW06035R10JNEA" 0603 7757.99,1467.28 r180 top value=2.20
R38 "ERJ-2RKF1003X" 0402 7696.5,2627.28 r270 top value=100k
R39 "ERJ-2RKF1003X" 0402 7701.5,1215.91 r270 top value=100k
R40 "RC0603FR-0724KL" 0603 4363.11,1644.33 r180 top value=24.0k
R41 "ERJ3EKF2001V" 0603 4051.61,1635.82 r270 bottom value=2.00k
R42 "CRCW060388K7FKEA" 0603 5208.11,1329.37 r270 bottom value=88.7k
R43 "RT0603BRD07243KL" 0603 5251.61,1795.82 r270 top value=243k
R44 "CRCW060322K1FKEA" 0603 5273.11,1329.37 r90 bottom value=22.1k
R45 "CRCW060322K1FKEA" 0603 5251.61,1795.82 r90 bottom value=22.1k
R46 "CSNL2512FTL500" 2512 9174.09,3462.28 r0 bottom value=0.0005
R47 "CRCW06035R10JNEA" 0603 7441.5,2913.78 r270 top value=2.20
R48 "CRCW06035R10JNEA" 0603 7406.5,1497.28 r90 top value=2.20
R49 "CSNL2512FTL500" 2512 9174.09,3632.28 r0 bottom value=0.0005
R50 "CSNL2512FTL500" 2512 9177.95,3802.28 r0 bottom value=0.0005
R51 "ERJ-2RKF1003X" 0402 7311.5,2632.28 r270 top value=100k
R52 "ERJ-2RKF1003X" 0402 7296.5,1218.66 r270 top value=100k
R53 "CRCW040210K0FKED" 0402 6713,4144.38 r90 bottom value=24k
R54 "CSNL2512FTL500" 2512 9174.09,3292.28 r0 bottom value=0.0005
R55 "CRCW040210K0FKED" 0402 6661.57,4017.19 r0 bottom value=10.0k
R56 "CRCW04022K00FKED" 0402 6385.38,4177 r0 bottom value=1.00k
R57 "ERJ-2RKF1001X" 0402 6467,4202.62 r90 bottom value=1.00k
R58 "CRCW040210K0FKED" 0402 6556,4012 r180 bottom value=10.0k
R59 "CRCW0402100RFKED" 0402 7256,4019.62 r270 top value=100
R64 "CRCW04023K60JNED" 0402 7336.5,3435.79 r90 top value=10.0k
R66 "CRCW04022K00FKED" 0402 7062.62,3331 r0 top value=1.00k
R67 "Resistor" 0402 6891.5,3552.28 r90 top value=10.0k
R68 "ERJ-2RKF1001X" 0402 7140.47,3353.66 r270 top value=1.00k
R70 "CRCW060310R0FKEA" 0603 8203,4113 r180 bottom value=10.0
R72 "CRCW060310R0FKEA" 0603 8201.5,4180 r180 bottom value=10.0
R74 "MCT06030Z0000ZP500" 0603 2045,3487.28 r180 top value=0
R76 "CRCW0402100RFKED" 0402 7424.09,3692.28 r270 bottom value=100
R77 "CRCW040210R0FKED" 0402 7446.5,3182.28 r270 top value=10.0
R78 "CRCW040210R0FKED" 0402 7417.87,3107.28 r0 top value=10.0
R79 "CRCW040210K0FKED" 0402 7391.5,3028.66 r90 top value=10.0k
R81 "CRCW040230R0JNED" 0402 7659.09,3557.28 r270 top value=30
R82 "CRCW040210K0FKED" 0402 7530.12,3207.28 r180 top value=10.0k
R83 "CRCW040230R0JNED" 0402 7919.09,3560.91 r270 top value=30
R84 "CRCW0402100RFKED" 0402 7495.12,4042.28 r180 top value=100
R85 "CRCW0402100RFKED" 0402 7312.65,4149.62 r90 top value=100
R86 "CRCW0402100RFKED" 0402 7409,4017.62 r270 top value=100
R89 "CRCW0402100RFKED" 0402 7284.09,3568.66 r90 top value=100
R90 "CRCW040210R0FKED" 0402 7506.5,1772.28 r270 top value=10.0
R91 "CRCW040210R0FKED" 0402 7456.5,1770.04 r270 top value=10.0
R92 "CRCW040210K0FKED" 0402 7421.5,1619.69 r90 top value=10.0k
R93 "CRCW040210K0FKED" 0402 7586.5,1747.28 r180 top value=10.0k
R97 "CRCW0402100RFKED" 0402 6300,3566.65 r90 top value=100
R98 "CRCW0402100RFKED" 0402 6255,3770 r0 bottom value=100
R101 "CRCW0402100RFKED" 0402 6004.09,4050.91 r270 top value=100
R102 "CRCW0402100RFKED" 0402 5926.5,4025.59 r0 top value=100
R103 "CRCW0402100RFKED" 0402 2658.9,3376.06 r180 top value=100
R104 "CRCW0402100RFKED" 0402 2060.12,3377.6 r180 top value=100
R105 "CRCW0402100RFKED" 0402 2658.9,3426.06 r180 top value=100
R106 "CRCW0402100RFKED" 0402 2061.5,3427.6 r180 top value=100
RT1 "TMP6131DECR" DEC0002A 6931.5,3572.28 r90 top
T2 "PAS6322.150NLT" FP-PAS6322.150NLT_SMT6_20MM5_12MM8-MFG 2372.68,2912.28 r270 top
T3 "750344367" Wurth_750315894 4831.61,1839.33 r0 top
U1 "OPA320AIDBVR" DBV0005A_N 8268.62,3867.46 r90 top
U2 "OPA320AIDBVR" DBV0005A_N 7597.36,4139.69 r180 top
U3 "OPA320AIDBVR" DBV0005A_N 7596.69,3416.42 r270 top
U4 "AMC1302QDWVRQ1" DWV0008A 2360.91,3887.28 r0 top
U5 "AMC1311BDWVR" DWV0008A 2360.91,3737.28 r0 bottom
U6 "UCC28911DR" D0007A_N 4151.02,1674.33 r0 top
U7 "TPS560430XDBVR" DBV0006A_N 5398.11,1322.87 r0 bottom
U8 "TPS560430XDBVR" DBV0006A_N 5391.61,1799.33 r0 bottom
U9 "TPS62163DSGR" DSG0008A 1817.6,4017.53 r0 top
U10 "LMV116MF/NOPB" DBV0005A_N 6564.4,4171.87 r90 bottom
U12 "INA214AIDCKR" DCK0006A_N 8012.72,4138.81 r0 bottom
U13 "LMV116MF/NOPB" DBV0005A_N 7239.09,3417.28 r270 top
U14 "UCC27211AQDDARQ1" DDA0008E_L 7609.84,3022.28 r180 top
U15 "UCC27211AQDDARQ1" DDA0008E_L 7581.5,1617.28 r180 top
U16 "TPS62163DSGR" DSG0008A 6461.97,3409.88 r90 top
U18 "ISO7742FQDWRQ1" DW0016B_HV 2359.09,3402.28 r180 top
U19 "TLV71333PQDBVRQ1" DBV0005A_N 6784.09,3372.28 r0 top
U20 "REF2033AIDDCR" DDC0005A_N 6785.63,3449.88 r180 bottom

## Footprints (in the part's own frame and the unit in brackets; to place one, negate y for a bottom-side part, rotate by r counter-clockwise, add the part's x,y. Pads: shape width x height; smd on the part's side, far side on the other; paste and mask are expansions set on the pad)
0402 [mm] "0402 from SM-752 data"
  rect 0.8x0.6 smd: 1(-0.6,0) 2(0.6,0)
  silkscreen extent -1.22,-0.52 1.22,0.52, body extent -0.55,-0.3 0.55,0.3, height 0.6
0603 [mm] "0603 from SM-752 data"
  rect 1x0.95 smd: 1(-0.8,0) 2(0.8,0)
  silkscreen extent -1.52,-0.69 1.52,0.69, body extent -0.87,-0.47 0.87,0.47, height 1
0603S [mil]
  rect 20x35 smd: 1(-30,0) 2(30,0)
  body extent -34,-19 34,19, height 39
0805_HV [mil] "0805 with 30mil clearance between pads"
  rect 50x63 smd: 1(-40,0) 2(40,0)
  silkscreen extent -74,-40 74,40, body extent -43,-29 43,29, height 57
1206 [mm] "1206 from SM-752 data"
  rect 1.3x1.85 smd: 1(-1.45,0) 2(1.45,0)
  silkscreen extent -2.4,-1.21 2.4,1.21, body extent -1.7,-0.9 1.7,0.9, height 1.35
1206_190 [mm] "1206_190"
  rect 1.1x1.6 smd: 1(-1.7,0) 2(1.7,0)
  silkscreen extent -0.9,-1 0.9,1, body extent -1.75,-0.95 1.75,0.95, height 1.9
1210_200 [mm] "1210"
  rect 1.3x2.7 smd: 1(-1.45,0) 2(1.45,0)
  silkscreen extent -2.32,-1.57 2.32,1.57, body extent -1.7,-1.35 1.7,1.35, height 2
1210_270 [mm] "1210"
  rect 1.3x2.7 smd: 1(-1.45,0) 2(1.45,0)
  silkscreen extent -2.32,-1.57 2.32,1.57, body extent -1.7,-1.35 1.7,1.35, height 2.7
1210_280 [mm] "SMD, 2-Leads, Body 3.6x2.8mm, Height 2.8mm"
  rect 1.1x2.2 smd: 1(-1.65,0) 2(1.65,0)
  silkscreen extent -0.84,-1.4 0.84,1.4, body extent -1.8,-1.4 1.8,1.4, height 2.8
2512 [mm] "Chip Resistor, Body 6.3x3.2mm, IPC Medium Density"
  rect 1.3x3.4 smd: 1(-2.95,0) 2(2.95,0)
  silkscreen extent -1.9,-1.6 1.9,1.6, body extent -3.22,-1.67 3.22,1.67, height 0.71
BXW_1800x4500#1 [mm] "TH, 2-Leads, Dia 18mm, Pin Spacing 7.5mm"
  round 1.55 hole 1.05: 2(3.75,0)
  rect 1.55x1.55 hole 1.05: HVBUS(-3.75,0)
  silkscreen extent -9.25,-9.25 9.25,9.25, body extent -9.25,-9.25 9.26,9.25, height 47.01
BXW_1800x4500#2 [mm] "TH, 2-Leads, Dia 18mm, Pin Spacing 7.5mm"
  rect 1.55x1.55 hole 1.05: 1(-3.75,0)
  round 1.55 hole 1.05: 2(3.75,0)
  silkscreen extent -9.25,-9.25 9.25,9.25, body extent -9.25,-9.25 9.26,9.25, height 47.01
controlCARD-120HSEC [mm] "Pads are not numbered according to Samtec datasheet."
  rect 0.5x2.724 smd: 1(-23.357,-1.678) 2(-23.357,1.722) 3(-22.557,-1.678) 4(-22.557,1.722) 5(-21.757,-1.678) 6(-21.757,1.722) 7(-20.957,-1.678) 8(-20.957,1.722) 9(-20.157,-1.678) 10(-20.157,1.722) 11(-19.357,-1.678) 12(-19.357,1.722) 13(-18.557,-1.678) 14(-18.557,1.722) 15(-17.757,-1.678) 16(-17.757,1.722) 17(-16.957,-1.678) 18(-16.957,1.722) 19(-16.157,-1.678) 20(-16.157,1.722) 21(-15.357,-1.678) 22(-15.357,1.722) 23(-14.557,-1.678) 24(-14.557,1.722) 25(-13.757,-1.678) 26(-13.757,1.722) 27(-12.957,-1.678) 28(-12.957,1.722) 29(-12.157,-1.678) 30(-12.157,1.722) 31(-11.357,-1.678) 32(-11.357,1.722) 33(-10.557,-1.678) 34(-10.557,1.722) 35(-9.757,-1.678) 36(-9.757,1.722) 37(-8.957,-1.678) 38(-8.957,1.722) 39(-8.157,-1.678) 40(-8.157,1.722) 41(-7.357,-1.678) 42(-7.357,1.722) 43(-6.557,-1.678) 44(-6.557,1.722) 45(-5.757,-1.678) 46(-5.757,1.722) 47(-4.957,-1.678) 48(-4.957,1.722) 49(-4.157,-1.678) 50(-4.157,1.722) 51(-3.357,-1.678) 52(-3.357,1.722) 53(-2.557,-1.678) 54(-2.557,1.722) 55(-1.757,-1.678) 56(-1.757,1.722) 57(2.243,-1.678) 58(2.243,1.722) 59(3.043,-1.678) 60(3.043,1.722) 61(3.843,-1.678) 62(3.843,1.722) 63(4.643,-1.678) 64(4.643,1.722) 65(5.443,-1.678) 66(5.443,1.722) 67(6.243,-1.678) 68(6.243,1.722) 69(7.043,-1.678) 70(7.043,1.722) 71(7.843,-1.678) 72(7.843,1.722) 73(8.643,-1.678) 74(8.643,1.722) 75(9.443,-1.678) 76(9.443,1.722) 77(10.243,-1.678) 78(10.243,1.722) 79(11.043,-1.678) 80(11.043,1.722) 81(11.843,-1.678) 82(11.843,1.722) 83(12.643,-1.678) 84(12.643,1.722) 85(13.443,-1.678) 86(13.443,1.722) 87(14.243,-1.678) 88(14.243,1.722) 89(15.043,-1.678) 90(15.043,1.722) 91(15.843,-1.678) 92(15.843,1.722) 93(16.643,-1.678) 94(16.643,1.722) 95(17.443,-1.678) 96(17.443,1.722) 97(18.243,-1.678) 98(18.243,1.722) 99(19.043,-1.678) 100(19.043,1.722) 101(19.843,-1.678) 102(19.843,1.722) 103(20.643,-1.678) 104(20.643,1.722) 105(21.443,-1.678) 106(21.443,1.722) 107(22.243,-1.678) 108(22.243,1.722) 109(23.043,-1.678) 110(23.043,1.722) 111(23.843,-1.678) 112(23.843,1.722) 113(24.643,-1.678) 114(24.643,1.722) 115(25.443,-1.678) 116(25.443,1.722) 117(26.243,-1.678) 118(26.243,1.722) 119(27.043,-1.678) 120(27.043,1.722)
  round 0.025 hole 1.27 unplated mask+0.876: 181(-24.857,0.022) 182(28.543,1.522)
  round 1.348 hole 0.84: 185(-27.207,0.022) 186(30.893,0.022)
  silkscreen extent -32.11,-3.86 35.8,3.9, body extent -31.75,-3.48 35.3,3.52, height 12.35
D0007A_N [mm] "SOIC, 7-Leads, Body 4.9x3.9mm, Pitch 1.27mm, IPC Medium Density"
  oval 1.45x0.6 smd: 1(-2.725,1.905) 2(-2.725,0.635) 3(-2.725,-0.635) 4(-2.725,-1.905) 5(2.725,-1.905) 6(2.725,-0.635) 8(2.725,1.905)
  silkscreen extent -3.32,-2.5 1.1,2.52, body extent -3.01,-2.45 3.01,2.45, height 1.75
DBV0005A_N [mm] "SOT23, 5-Leads, Body 2.9x1.6mm, Pitch 0.95mm, Lead Span 2.8mm, IPC Medium Density"
  rrect17% 1x0.6 smd: 1(-1.375,0.95) 2(-1.375,0) 3(-1.375,-0.95) 4(1.375,-0.95) 5(1.375,0.95)
  silkscreen extent -0.25,-1.55 0.25,1.55, body extent -1.42,-1.46 1.42,1.46, height 1.09
DBV0006A_N [mm] "SOT23, 6-Leads, Body 2.9x1.6mm, Pitch 0.95mm, Lead Span 2.8mm, IPC Medium Density"
  rrect17% 1x0.6 smd: 1(-1.375,0.95) 2(-1.375,0) 3(-1.375,-0.95) 4(1.375,-0.95) 5(1.375,0) 6(1.375,0.95)
  silkscreen extent -1.68,-1.55 0.5,1.55, body extent -1.42,-1.46 1.42,1.46, height 1.12
DCK0006A_N [mm] "SOT23, 6-Leads, Body 2x1.3mm, Pitch 0.65mm, Lead Span 2.1mm, IPC Medium Density"
  rrect25% 0.85x0.4 smd: 1(-1.125,0.65) 2(-1.125,0) 3(-1.125,-0.65) 4(1.125,-0.65) 5(1.125,0) 6(1.125,0.65)
  silkscreen extent -1.5,-1.09 0.51,1.09, body extent -1.14,-1 1.14,1, height 0.95
DDA0008E_L [mm]
  rrect18% 1.25x0.55 smd: 1(-2.625,1.905) 2(-2.625,0.635) 3(-2.625,-0.635) 4(-2.625,-1.905) 5(2.625,-1.905) 6(2.625,-0.635) 7(2.625,0.635) 8(2.625,1.905)
  rrect7% 2.95x4.9 smd paste-1.5 mask-1.5: 9(0,0)
  rrect4% 2.4x3.1 on Top Paste: 9(0,0)
  rrect4% 2.4x3.1 on Top Solder: 9(0,0)
  silkscreen extent -3.13,-2.5 1.4,2.5, body extent -3,-2.45 3,2.45, height 1.57
DDC0005A_N [mm]
  rrect17% 1x0.6 smd: 1(-1.375,0.95) 2(-1.375,0) 3(-1.375,-0.95) 4(1.375,-0.95) 5(1.375,0.95)
  silkscreen extent -1.25,-1.52 0.88,1.57, body extent -1.41,-1.45 1.41,1.45, height 1.1
DEC0002A [mm] "X1SON-2"
  rrect57% 0.35x0.6 smd paste-0.5 mask-0.05: 1(-0.325,0) 2(0.325,0)
  rrect33% 0.3x0.5 on Top Paste: 1S(-0.35,0) 2S(0.35,0)
  body extent -0.5,-0.3 0.5,0.3, height 0.5
DNK0008A [mm] "SON, 8-Leads, Body 5x6mm"
  rrect39% 0.86x0.51 smd paste-0.05 mask-0.05: 1(-2.82,1.905) 2(-2.82,0.635) 3(-2.82,-0.635) 4(-2.82,-1.905) 5(2.82,-1.905) 6(2.82,-0.635) 7(2.82,0.635) 8(2.82,1.905)
  rrect8% 1.48x1.27 on Top Paste: 9(-0.18,-1.47) 9(-0.18,0) 9(-0.18,1.47) 9(1.5,-1.47) 9(1.5,0) 9(1.5,1.47)
  rrect5% 4.34x4.6 smd paste-3 mask-0.05: 9(1.08,0)
  silkscreen extent -3.2,-2.7 3.2,2.7, body extent -3.05,-2.55 3.05,2.55, height 1.06
DSG0008A [mm] "SON, 8-Leads, Body 2x2mm, Pitch 0.5mm, Thermal Pad 1.6x0.9mm, TI Recommended"
  rrect40% 0.5x0.25 smd: 1(-0.95,0.75) 2(-0.95,0.25) 3(-0.95,-0.25) 4(-0.95,-0.75) 5(0.95,-0.75) 6(0.95,-0.25) 7(0.95,0.25) 8(0.95,0.75)
  rrect14% 0.9x0.7 on Top Paste: 9(0,-0.45) 9(0,0.45)
  rrect11% 0.9x1.6 smd paste-0.45: 9(0,0)
  silkscreen extent -1.07,-1.15 1.07,1.15, body extent -1,-1 1,1, height 0.77
DW0016B_HV [mm] "SOIC-16, HV/isolation option"
  rrect17% 1.65x0.6 smd: 1(-4.875,4.445) 2(-4.875,3.175) 3(-4.875,1.905) 4(-4.875,0.635) 5(-4.875,-0.635) 6(-4.875,-1.905) 7(-4.875,-3.175) 8(-4.875,-4.445) 9(4.875,-4.445) 10(4.875,-3.175) 11(4.875,-1.905) 12(4.875,-0.635) 13(4.875,0.635) 14(4.875,1.905) 15(4.875,3.175) 16(4.875,4.445)
  body extent -5.17,-5.15 5.17,5.15, height 2.59
DWV0008A [mm] "SOIC, 8-Leads, Body 5.95x7.6mm (max), Pitch 1.27mm"
  rrect17% 1.8x0.6 smd: 1(-5.45,1.905) 2(-5.45,0.635) 3(-5.45,-0.635) 4(-5.45,-1.905) 5(5.45,-1.905) 6(5.45,-0.635) 7(5.45,0.635) 8(5.45,1.905)
  silkscreen extent -6.25,-2.95 2.98,2.95, body extent -5.77,-2.92 5.77,2.93, height 2.67
FP-74438336010_SMD2-MFG [mm]
  rrect8% 1.3x3.4 smd paste+0 mask+0: 1(-1.05,0) 2(1.05,0)
  silkscreen extent -1.6,-2.1 1.6,2.1, body extent -1.8,-1.8 1.8,1.8, height 0.25
FP-C4532C0G2E104J320KN_1812-MFG [mm]
  rrect8% 1.3x2.8 smd paste+0 mask+0: 1(-2.35,0) 2(2.35,0)
  silkscreen extent -2.45,-1.8 2.45,1.8, body extent -2.25,-1.6 2.25,1.6, height 3.6
FP-CGA6P1C0G3A103J250AC_1210-MFG [mm]
  rrect9% 1.1x2.2 smd paste+0 mask+0: 1(-1.65,0) 2(1.65,0)
  silkscreen extent -0.72,-1.4 0.72,1.4, body extent -1.6,-1.25 1.6,1.25, height 2.81
FP-CKG57NC0G2E304J500JH_2220-MFG [mm]
  rrect6% 1.75x4.75 smd paste+0 mask+0: 1(-2.925,0) 2(2.925,0)
  silkscreen extent -1.68,-2.75 1.68,2.75, body extent -3,-2.5 3,2.5, height 5.5
FP-EGPD800ELL102ML35H_RADIAL-MFG [mm]
  rrect7% 1.45x1.45 hole 0.95 paste-1000 mask+0: 1(-3.75,0)
  round 1.45 hole 0.95 paste-1000 mask+0: 2(3.75,0)
  silkscreen extent -8.25,-8.25 8.25,8.25, body extent -8.35,-8.35 8.35,8.35, height 0.25
FP-FLE-102-01-G-DV_HDR4-MFG [mm]
  rrect14% 0.74x1.675 smd paste+0 mask+0: 1(-0.635,1.843) 2(-0.635,-1.843) 3(0.635,1.843) 4(0.635,-1.843)
  silkscreen extent -1.4,-1.73 1.4,3.35, body extent -1.5,-2.78 1.5,2.78, height 0.25
FP-GRM31CC72A475KE11L_1206-MFG [mm]
  rrect9% 1.15x1.8 smd paste+0 mask+0: 1(-1.575,0) 2(1.575,0)
  silkscreen extent -0.63,-0.95 0.63,0.95, body extent -2.25,-1.05 2.25,1.05, height 0.25
FP-M50-3000445_CONN_SCKT_STRP8-MFG [mm]
  rrect9% 1.12x1.12 hole 0.7 paste-1000 mask+0: 1(-1.905,-0.635)
  round 1.12 hole 0.7 paste-1000 mask+0: 2(-1.905,0.635) 3(-0.635,-0.635) 4(-0.635,0.635) 5(0.635,-0.635) 6(0.635,0.635) 7(1.905,-0.635) 8(1.905,0.635)
  silkscreen extent -2.89,-2.23 2.89,1.63, body extent -2.99,-1.73 2.99,1.73, height 0.25
FP-PAS6322.150NLT_SMT6_20MM5_12MM8-MFG [mm]
  rrect4% 3.5x2.7 smd paste+0 mask+0: 1(-2.75,-8.8) 2(2.75,-8.8)
  rrect8% 1.2x1.7 smd paste+0 mask+0: 3(3.75,9.3) 4(1.25,9.3) 5(-1.25,9.3) 6(-3.75,9.3)
  silkscreen extent -6.4,-10.85 6.4,7.55, body extent -6.39,-10.25 6.4,10.25, height 7.01
FP-RT0402BRD076K34L_0402-MFG [mm]
  rrect20% 0.5x0.6 smd paste+0 mask+0: 1(-0.5,0) 2(0.5,0)
  silkscreen extent -0.5,-0.71 0.5,0.7, body extent -0.85,-0.4 0.85,0.4, height 0.25
Keystone5000 [mil] "For Keystone 500x miniature loop terminals"
  round 80 hole 40: 1(0,0)
  silkscreen extent -52,-52 52,52, body extent -49,-49 49,49, height 182
Keystone5001 [mil] "For Keystone 500x miniature loop terminals"
  round 80 hole 40: 1(0,0)
  silkscreen extent -52,-52 52,52, body extent -49,-49 49,49, height 182
KY_700x500x1000 [mm] "TH, 2- Leads, Body 7x5mm, Pin Spacing 7.5mm"
  round 1.4 hole 0.9: 1(-3.75,0) 2(3.75,0)
  silkscreen extent -3.5,-2.5 3.5,2.5, body extent -4.05,-2.5 4.05,2.5, height 9.97
Mill-Max_0312-0-15-15-34-27-10-0 [mm] "Pin Receptacle, .032-.046\" .075\" Dia, Gold, TH"
  round 2.45 hole 1.905: 1(0,0)
  silkscreen extent -1.52,-1.52 1.52,1.52, body extent -1.15,-1.15 1.16,1.15, height 0.46
Molex_90122-0763 [mm] "Header, 2.54mm, 3x2, R/A, TH"
  rrect50% 1.5x1.5 hole 1: 1(-1.27,2.54)
  round 1.5 hole 1: 2(1.27,2.54) 3(-1.27,0) 4(1.27,0) 5(-1.27,-2.54) 6(1.27,-2.54)
  silkscreen extent -5.6,-3.9 -2.6,3.9, body extent -12.27,-3.81 1.57,3.81, height 6.35
Panasonic_D8 [mm] "SMD, 2-Leads, Dia 6.3mm"
  rect 3.2x1.6 smd: 1(-2.5,0) 2(2.5,0)
  silkscreen extent -3.4,-3.4 3.4,3.4, body extent -3.4,-3.4 3.4,3.4, height 8.01
PowerDI123 [mm] "Diodes Inc recommended land pattern, document number DS30628 Rev. 6-2"
  rect 2.2x1.4 smd: 1(-1.275,0)
  rect 0.9x1.4 smd: 2(1.275,0)
  silkscreen extent -3.1,-1.09 1.76,1.09, body extent -2.38,-0.97 1.52,0.96, height 1
Samtec_SSW-106-01-x-S [mm] "Receptacle, 6x1, 2.54mm, TH"
  rect 1.55x1.55 hole 1.04: 1(-6.35,0)
  round 1.55 hole 1.04: 2(-3.81,0) 3(-1.27,0) 4(1.27,0) 5(3.81,0) 6(6.35,0)
  silkscreen extent -8.2,-1.21 7.87,1.21, body extent -7.87,-1.21 7.87,1.21, height 8.51
SMA [mm] "Molded Diode, 2-Leads, Body 4.3x2.6mm, IPC Medium Density, based on OnSemi component dimensions and land pattern"
  rect 2x2 smd: 1(-2,0) 2(2,0)
  silkscreen extent -3.66,-1.57 2.79,1.57, body extent -2.6,-1.3 2.6,1.3, height 2.42
SOD-123 [mm] "On Semi recommended land pattern"
  rect 0.915x1.22 smd: 1(-1.637,0) 2(1.637,0)
  silkscreen extent -2.74,-1.17 2.03,1.17, body extent -1.93,-0.9 1.93,0.9, height 1.35
SOD-123H [mm] "SMT, 2-Leads, Body 3.5x1.6mm"
  rect 1.3x1.8 smd: 1(-1.5,0) 2(1.5,0)
  silkscreen extent -2.9,-1.3 2.3,1.3, body extent -1.9,-0.9 1.9,0.9, height 1
SOD-323 [mm] "NXP recommended land pattern"
  rect 0.6x0.6 smd paste-0.05: 1(-1.1,0) 2(1.1,0)
  silkscreen extent -2.06,-0.86 1.53,0.86, body extent -1.3,-0.67 1.3,0.68, height 1.1
SOT-23 [mm] "SOT23, 3-Leads, Body 2.9x1.3mm, Pitch 0.95mm, Lead Span 2.5mm, IPC Medium Density"
  rrect50% 1x0.6 smd: 1(-1.2,0.95) 2(-1.2,-0.95) 3(1.2,0)
  silkscreen extent -1.62,-1.5 0.7,1.5, body extent -1.16,-1.45 1.21,1.45, height 1
Sullins_PEC03SBAN [mm] "Sullins"
  rect 1.7x1.7 hole 1.16: 1(-2.54,0)
  round 1.7 hole 1.16: 2(0,0) 3(2.54,0)
  silkscreen extent -4.07,0.58 3.86,9.85, body extent -3.81,-0.29 3.81,9.94, height 3.56
Sullins_xxC02SBAN [mm] "Header, 2.54 mm, 2x1, R/A, TH"
  rect 1.55x1.55 hole 1.016: 1(-1.27,4.06)
  round 1.55 hole 1.016: 2(1.27,4.06)
  silkscreen extent -3,0.23 2.54,2.54, body extent -2.54,-5.84 2.54,4.38, height 3.56
Sullins_xxxC032LFBN-RC [mm] "Receptacle, 2.54mm, 3x2, TH"
  rrect50% 1.53x1.53 hole 1.02: 1(-2.54,1.27)
  round 1.53 hole 1.02: 2(-2.54,-1.27) 3(0,1.27) 4(0,-1.27) 5(2.54,1.27) 6(2.54,-1.27)
  body extent -4.06,-2.54 4.06,2.54, height 8.5
SVPF_E7 [mm] "Panasonic SVPF series"
  rect 4.15x1.9 smd: 1(-3.475,0) 2(3.475,0)
  silkscreen extent -4.24,-4.24 4.26,4.26, body extent -4.24,-4.24 4.26,4.26, height 7
TE_282856-2#1 [mm] "TH, 2-Leads, Body 10x10mm, Pitch 5mm"
  rect 1.9x1.9 hole 1.4: HVBUS(-2.5,0)
  round 1.9 hole 1.4: HVBUS(2.5,0)
  silkscreen extent -5.61,-5 5.5,5, body extent -5,-5 5.5,5, height 19
TE_282856-2#2 [mm] "TH, 2-Leads, Body 10x10mm, Pitch 5mm"
  rect 1.9x1.9 hole 1.4: 1(-2.5,0)
  round 1.9 hole 1.4: 2(2.5,0)
  silkscreen extent -5.61,-5 5.5,5, body extent -5,-5 5.5,5, height 19
VLS252010HBX [mm] "TDK"
  rect 0.6x2 smd: 1(-0.95,0) 2(0.95,0)
  silkscreen extent -0.25,-1.1 0.25,1.1, body extent -1.35,-1.1 1.35,1.1, height 1
WE-PD2A_4532 [mm] "WURTH"
  rrect50% 1.75x4.5 smd: 1(-1.625,0) 2(1.625,0)
  Top Layer region: 1.375,2.25 0.75,2.25 0.75,-2.25 1.375,-2.25
  Top Layer region: -1.375,-2.25 -0.75,-2.25 -0.75,2.25 -1.375,2.25
  silkscreen extent -0.4,-2.1 0.4,2.12, body extent -2.16,-2 2.16,2, height 3.2
Wurth_750315894 [mm] "TH, 10-Leads, Body 14.73x14.73mm, Pitch 2.5mm"
  rect 1.7x1.7 hole 1.2: 1(-7.75,6.4)
  round 1.7 hole 1.2: 2(-7.75,3.2) 3(-7.75,0) 4(-7.75,-3.2) 5(-7.75,-6.4) 6(7.75,-6.4) 7(7.75,-3.2) 8(7.75,0) 9(7.75,3.2) 10(7.75,6.4)
  silkscreen extent -10.04,-9 10,9, body extent -7.36,-7.36 7.37,7.37, height 15.24
Wurth_61300511021 [mm] "Header, 2.54 mm, 5x1, R/A, TH"
  rect 1.6x1.6 hole 1.1: 1(-5.08,0)
  round 1.6 hole 1.1: 2(-2.54,0) 3(0,0) 4(2.54,0) 5(5.08,0)
  silkscreen extent -6.75,-4.04 6.35,-1.5, body extent -6.35,-10.04 6.35,0.32, height 2.55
